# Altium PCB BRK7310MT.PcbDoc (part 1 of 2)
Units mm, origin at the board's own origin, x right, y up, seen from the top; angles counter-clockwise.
Board outline 140 x 100 mm, 6 copper layers (L1-TOP, L2-GND, L3-SIG, L4-SIG, L5-GND, L6-BOT), stack 1.39 mm thick; 75 components, 182 nets, 687 pads, 296 vias.
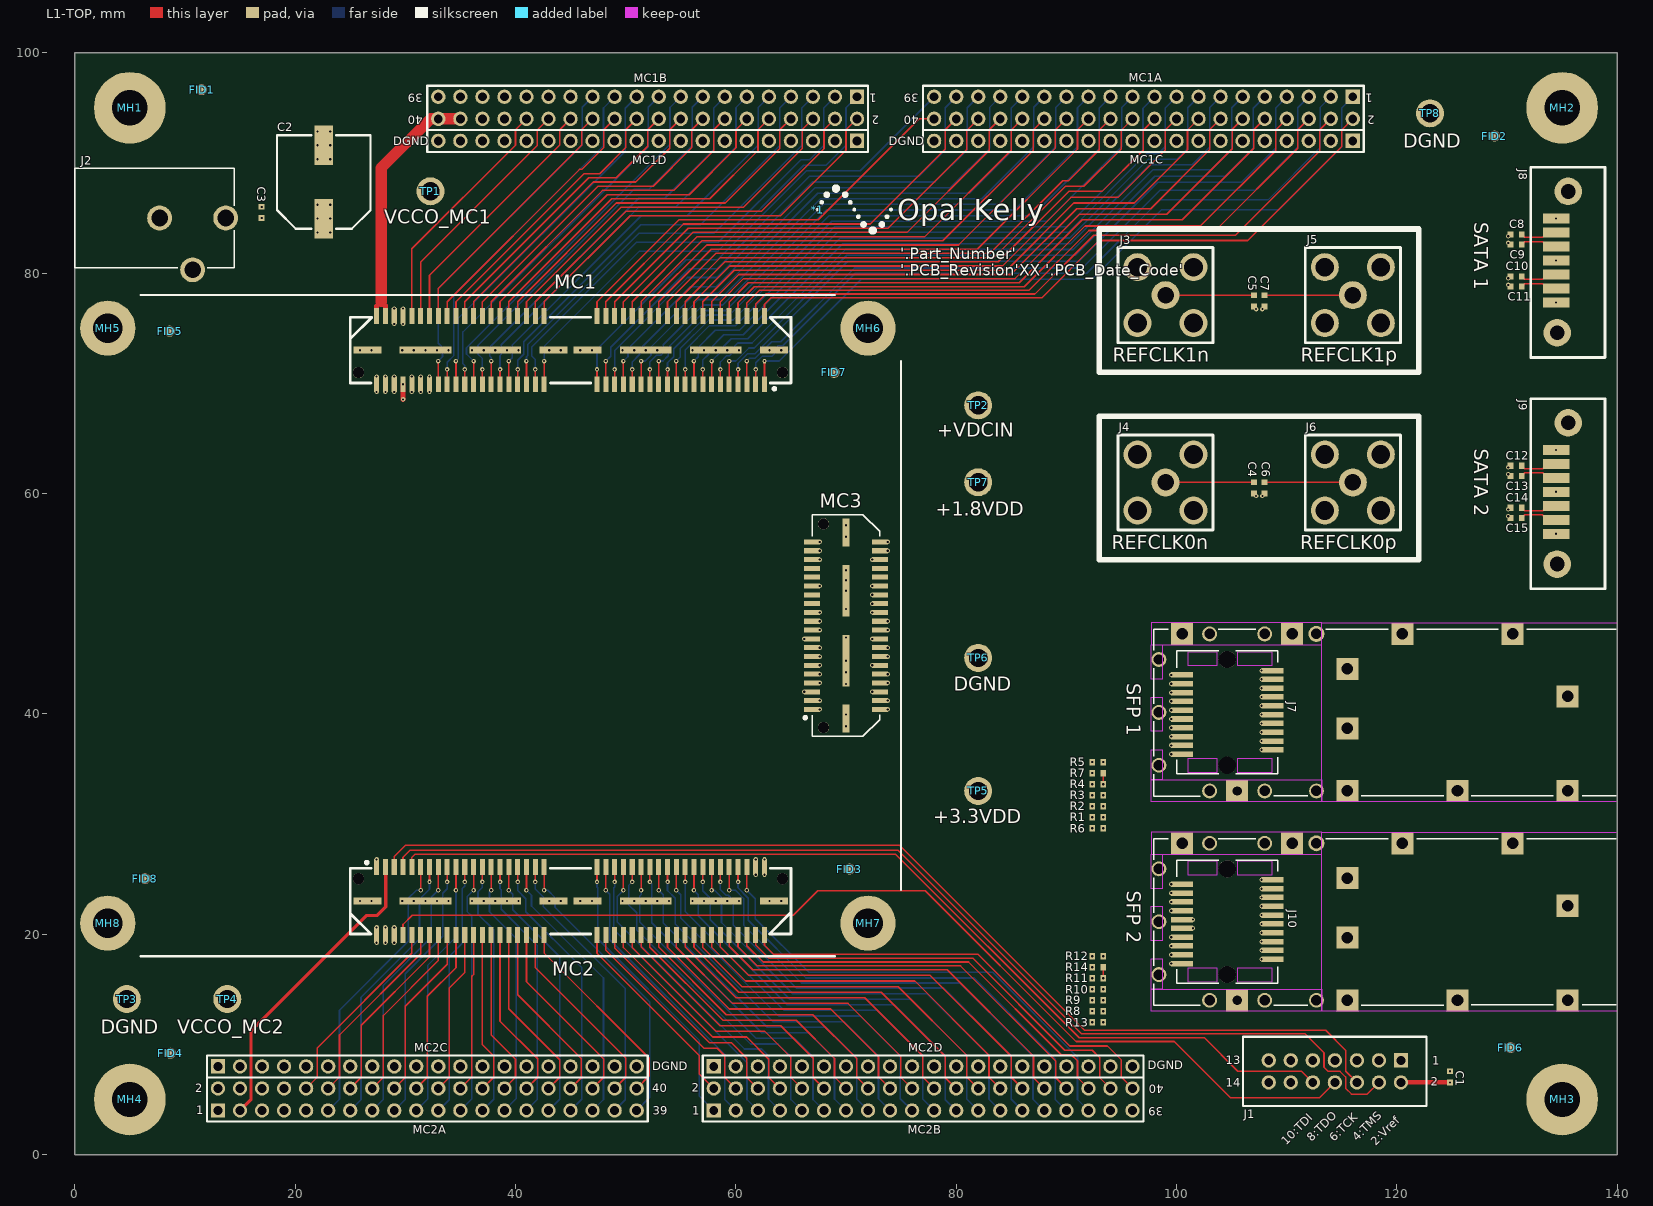
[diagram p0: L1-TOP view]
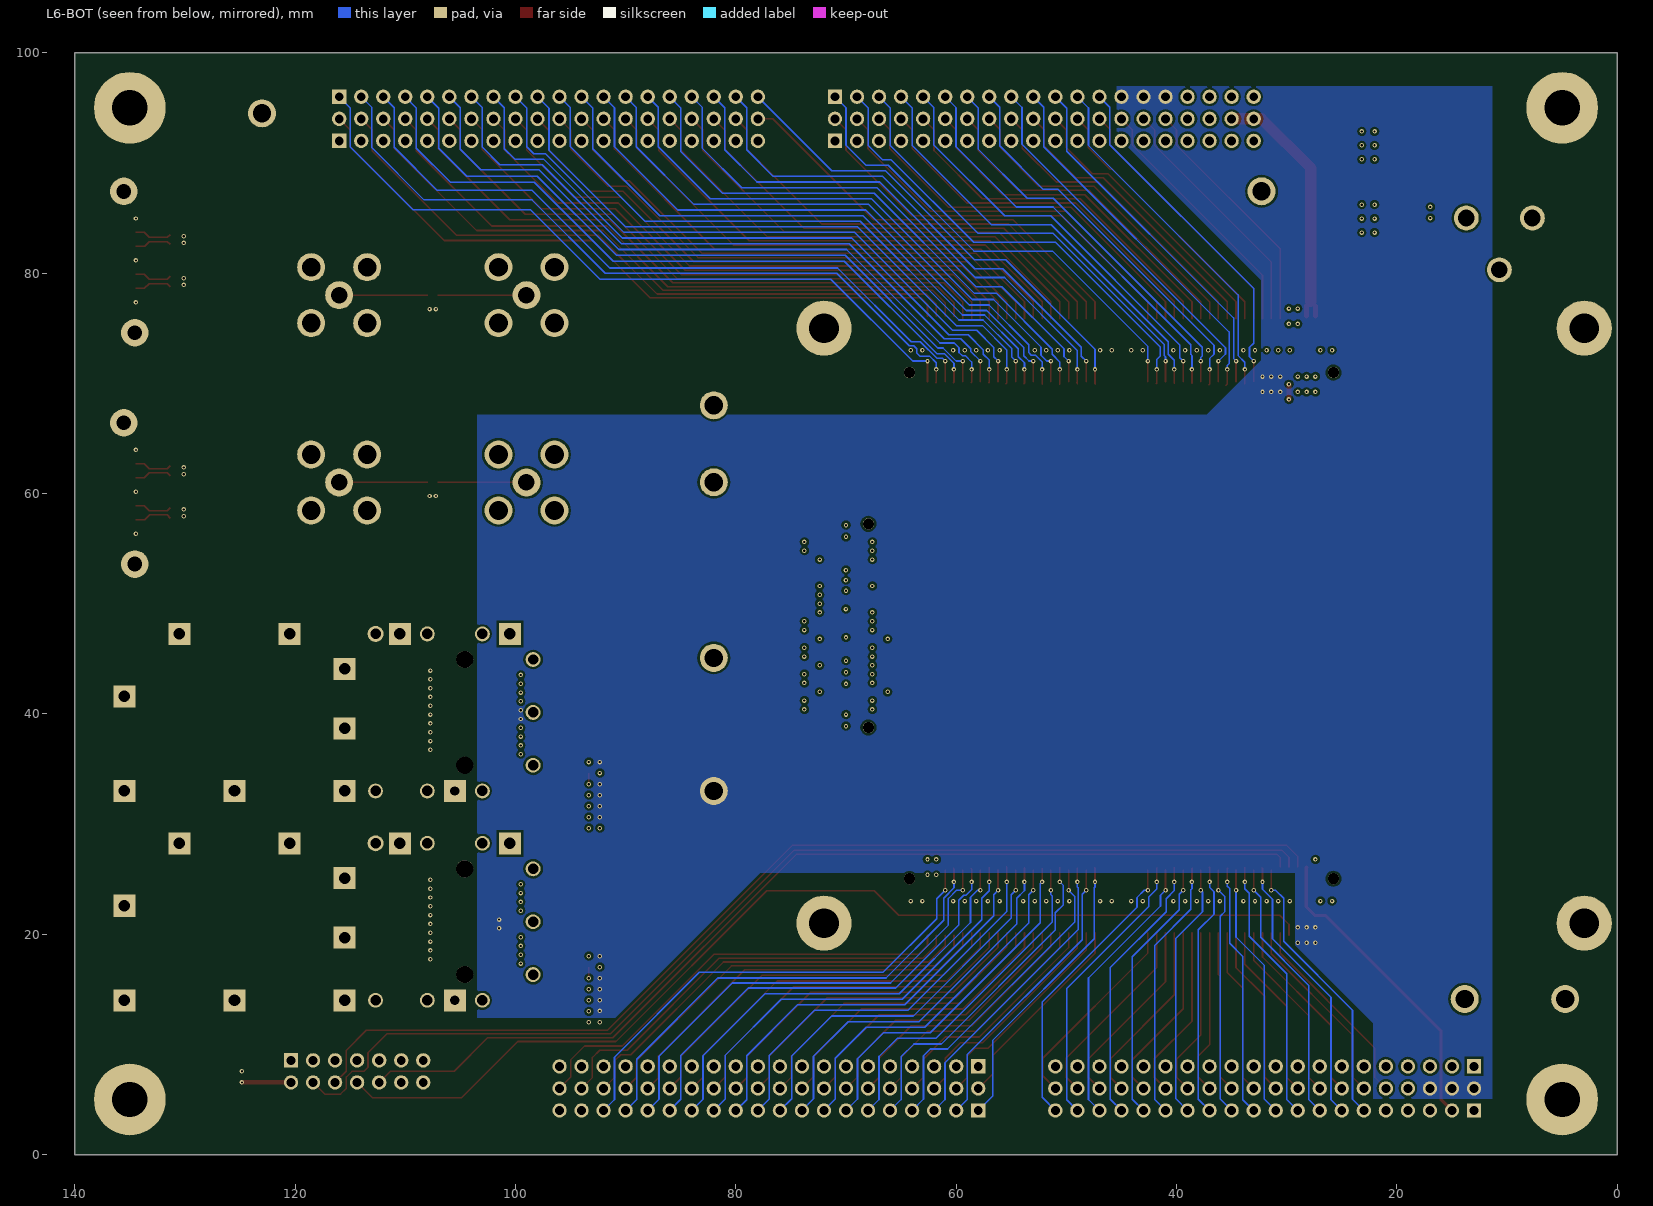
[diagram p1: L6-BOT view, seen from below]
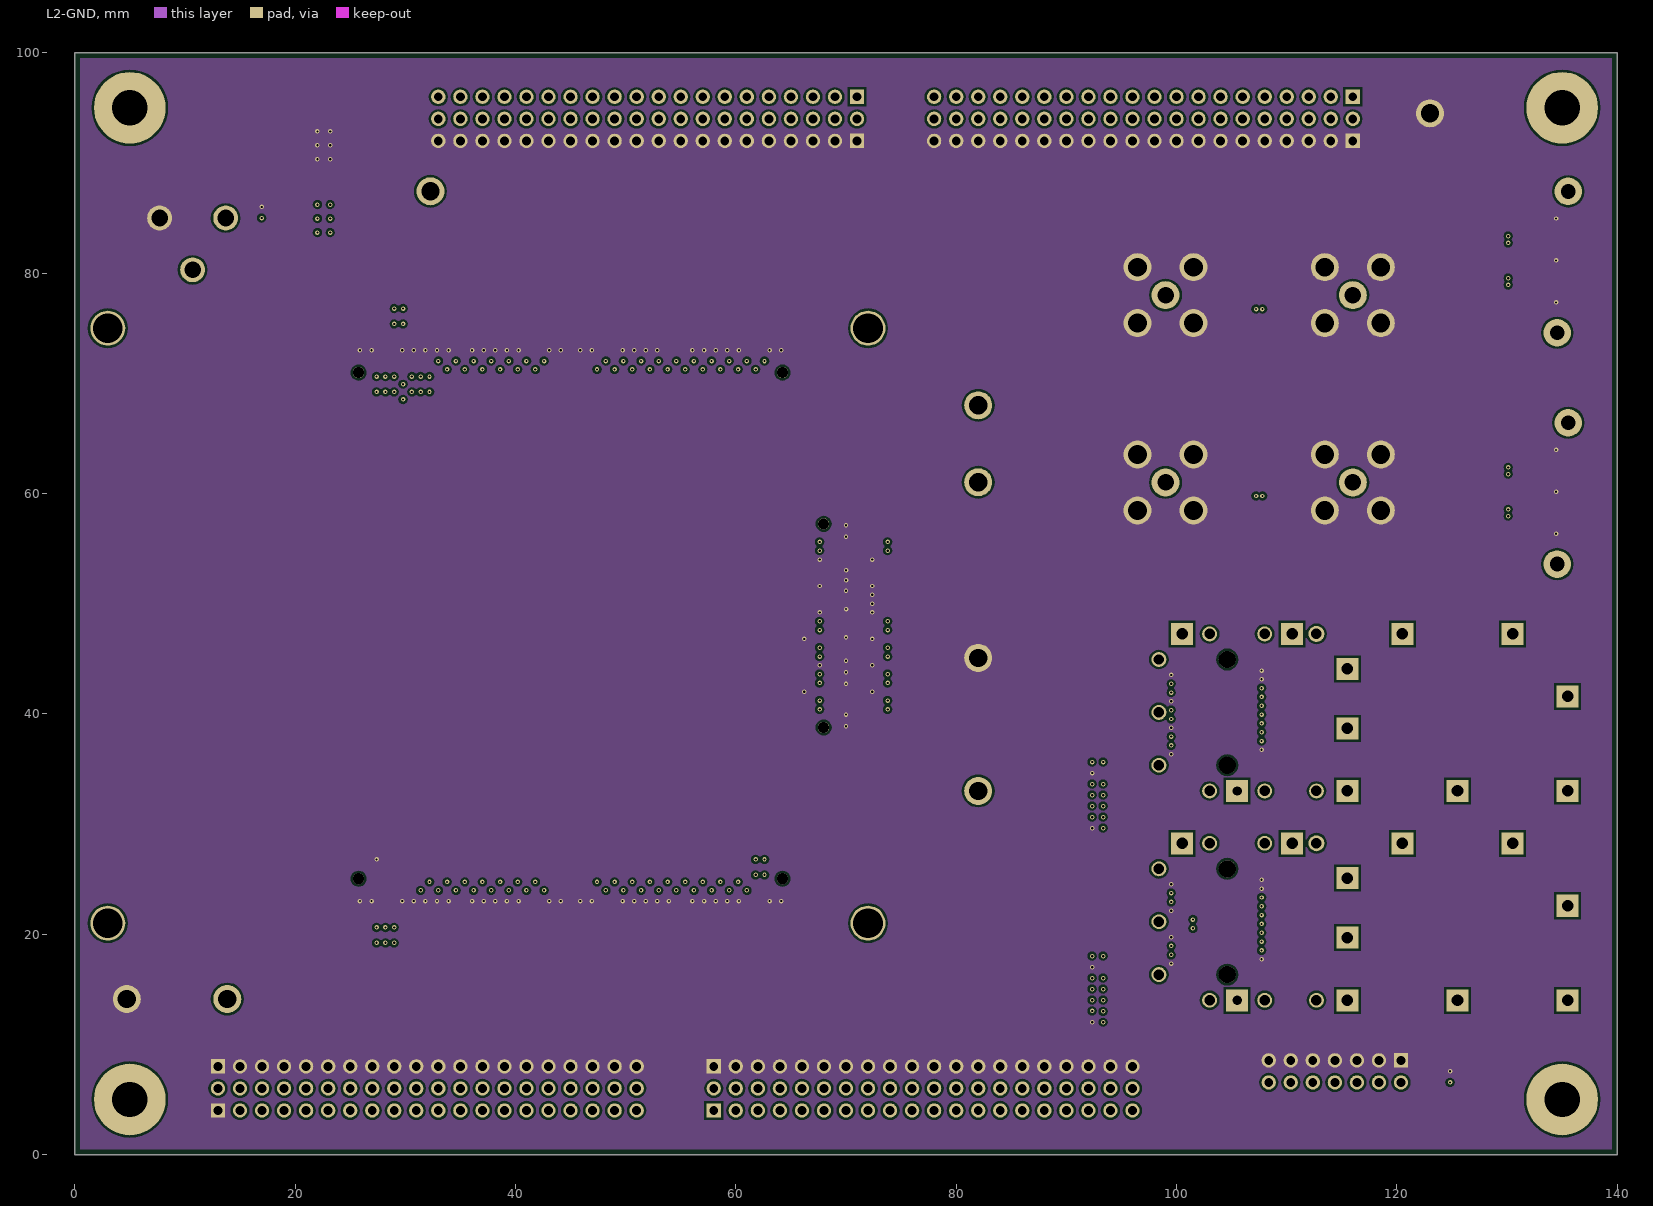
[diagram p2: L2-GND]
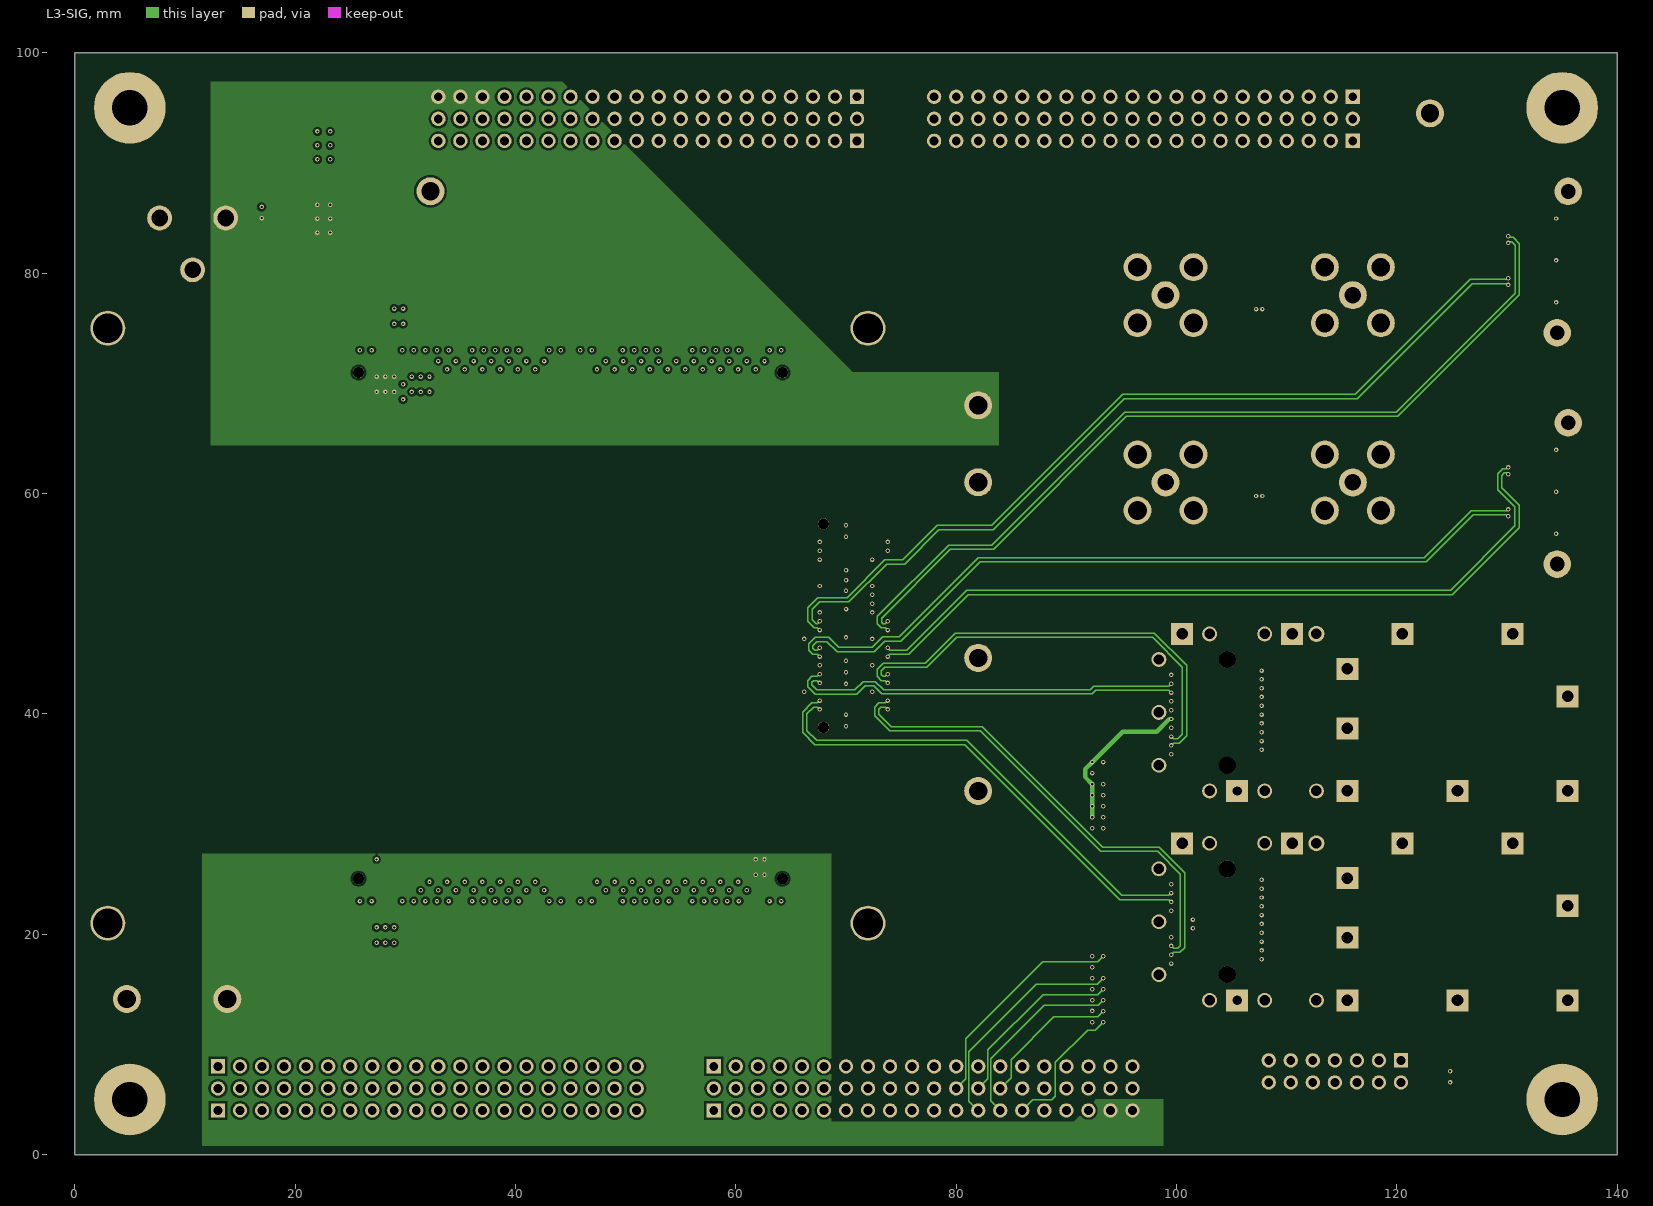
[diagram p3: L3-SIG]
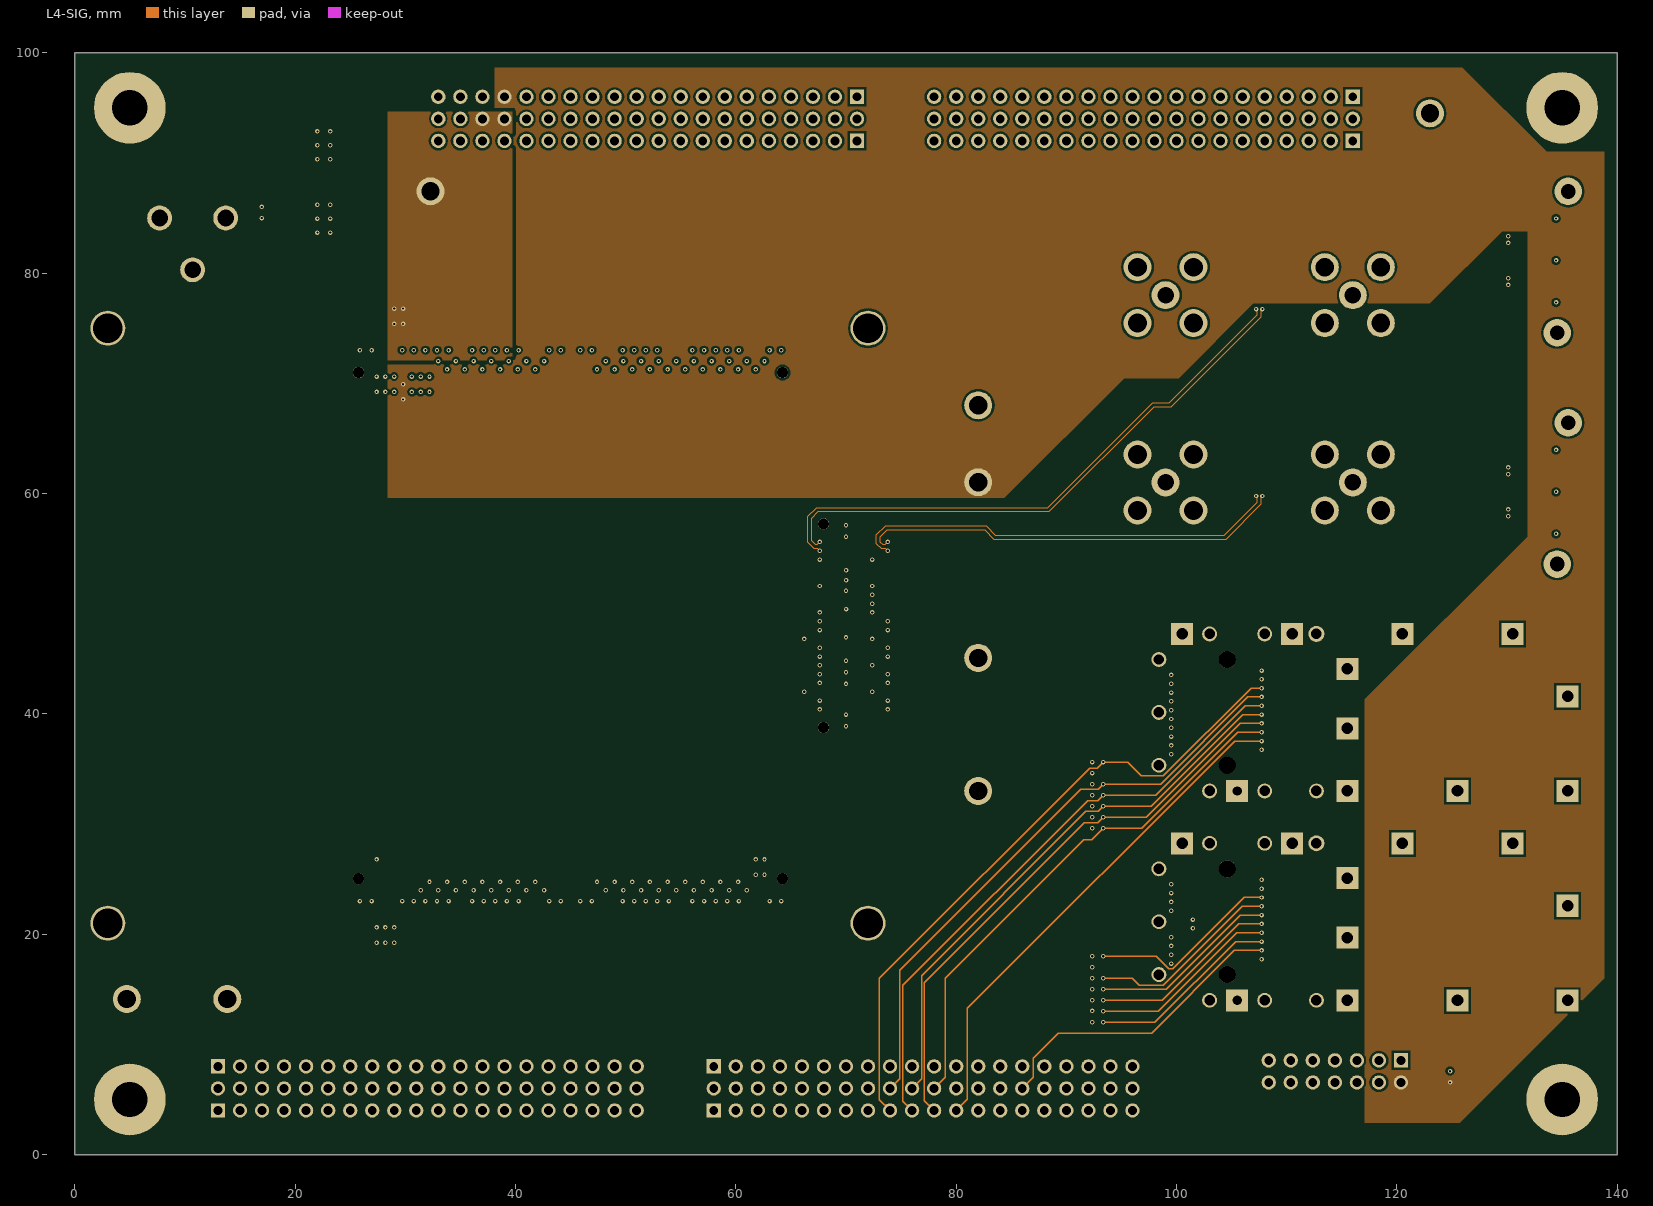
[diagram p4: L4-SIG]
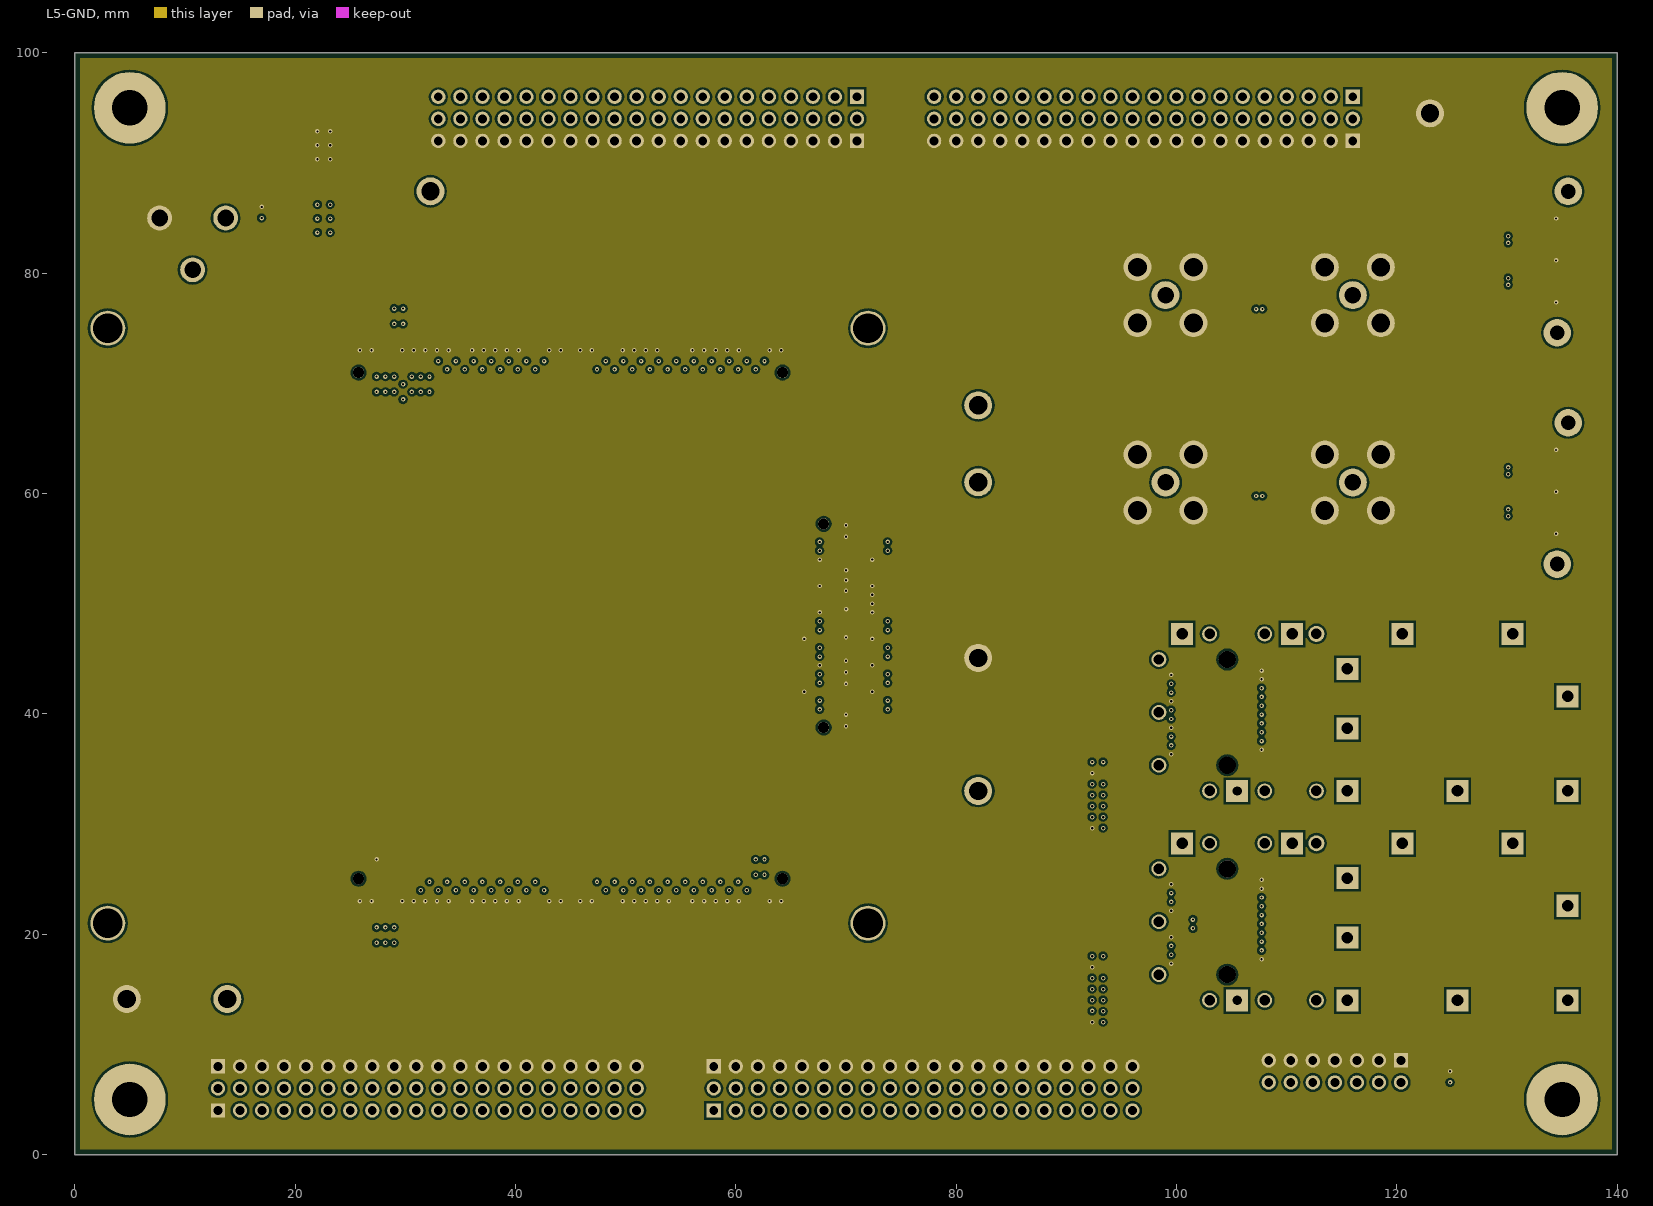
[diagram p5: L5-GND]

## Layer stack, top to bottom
Top Solder: solder mask 0.0203, Solder Resist, Dk 0
L1-TOP: signal copper 0.0356
Dielectric 2: prepreg 0.111, IT180A, Dk 4.12
L2-GND: signal copper 0.0356
Dielectric 5: core 0.0584, IT180A, Dk 4.12
L3-SIG: signal copper 0.0356
Dielectric 6: prepreg 0.8379, IT180A, Dk 4.2
L4-SIG: signal copper 0.0356
Dielectric 1: core 0.0584, IT180A, Dk 4.12
L5-GND: signal copper 0.0356
Dielectric 4: prepreg 0.111, IT180A, Dk 4.12
L6-BOT: signal copper 0.0356
Solder Side: solder mask 0.0203, Solder Resist, Dk 0

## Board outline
0,0 0,100 140,100 140,0

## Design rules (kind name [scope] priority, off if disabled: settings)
Clearance [All] p1: gap=0.127 ignorepadtopadclearanceinfootprint=FALSE except(0.114: SMDPad-Via Via-Via; 0.203: Arc-Poly SMDPad-Poly THPad-Poly Via-Fill Via-Poly Via-Region Fill-Poly Poly-Region Poly-Text Poly-Hole; 0.254: Track-Poly; 0.381: Poly-Poly)
DiffPairsRouting 100ohm_Diff [InDifferentialPairClass('100ohm_Diff')] p1: maxlimit=0.254 minlimit=0.248 mostfreqgap=0.254 toplayer_maxgap=0.248 toplayer_prefgap=0.248 toplayer_minwidth=0.133 toplayer_maxwidth=0.133 toplayer_prefwidth=0.133 midlayer1_mingap=0.254 midlayer1_minwidth=0.381 midlayer1_maxwidth=0.381 midlayer1_prefwidth=0.381 midlayer2_mingap=0.254 midlayer2_minwidth=0.127 midlayer2_maxwidth=0.127 midlayer2_prefwidth=0.127 midlayer3_mingap=0.254 midlayer3_minwidth=0.102 midlayer3_maxwidth=0.127 midlayer3_prefwidth=0.127 midlayer5_mingap=0.254 midlayer5_minwidth=0.381 midlayer5_maxwidth=0.381 midlayer5_prefwidth=0.381 bottomlayer_maxgap=0.248 bottomlayer_prefgap=0.248 bottomlayer_minwidth=0.133 bottomlayer_maxwidth=0.133 bottomlayer_prefwidth=0.133 maxuncoupledlength=8.89
FabricationTestPointUsage TestPointUsage [All] p1: valid=0 allowmultiple=FALSE
FabricationTestpoint Testpoint [All] p1: side=3 testpointundercomponent=TRUE minsize=1.016 maxsize=2.54 preferedsize=1.524 minholesize=0 maxholesize=1.016 preferedholesize=0.813 testpointgrid=0.025 allowsidetop=TRUE allowsidebottom=TRUE usegrid=TRUE gridtolerance=0
HoleSize [All] p1: absolutevalues=TRUE maxlimit=3.81 minlimit=0.203 maxpercent=80.000 minpercent=20.000
MatchedLengths okMatched_100ohm_Diff [InxSignalClass('xSignals_100ohm_Diff')] p1: tolerance=0.127 checknetsindiffpair=TRUE checkdiffpairvsdiffpair=FALSE checkxsignals=FALSE checkothers=FALSE
MinimumAnnularRing [All] p1: minimumring=0.102
MinimumSolderMaskSliver [All] p1: minsoldermaskwidth=0.048
PlaneClearance [All] p1: clearance=0.305
PlaneConnect [All] p1: planeconnectstyle=Direct reliefexpansion=0.508 reliefentries=4 reliefconductorwidth=0.254 reliefairgap=0.254
PolygonConnect "Via Connect" [IsVia] p1: connectstyle=Direct reliefconductorwidth=0.254 reliefentries=4 polygonreliefangle="90 Angle" airgapwidth=0.254
PolygonConnect [All] p2: connectstyle=Direct reliefconductorwidth=0.305 reliefentries=4 polygonreliefangle="90 Angle" airgapwidth=0.254
RoutingVias [All] p1: holewidth=0.203 width=0.406 viastyle="Through Hole" minholewidth=0.203 minwidth=0.406 maxholewidth=1.27 maxwidth=2.54
SilkToSilkClearance [All] p1: silktosilkclearance=0.003
SilkToSolderMaskClearance SilkscreenOverComponentPads [IsPad] p1: minsilkscreentomaskgap=0.051 clearancetoexposedcopper=TRUE
SolderMaskExpansion [All] p1: expansion=0.051
Width okWidth_50ohm [InNetClass('50ohm')] p1: maxlimit=0.254 minlimit=0.114 preferedwidth=0.117 toplayer_maxwidth=0.114 toplayer_prefwidth=0.114 midlayer1_minwidth=0.254 midlayer1_prefwidth=0.254 midlayer2_minwidth=0.117 midlayer2_maxwidth=0.117 midlayer3_minwidth=0.117 midlayer3_maxwidth=0.117 midlayer5_minwidth=0.254 midlayer5_prefwidth=0.254 bottomlayer_maxwidth=0.114 bottomlayer_prefwidth=0.114 minimp=50.000000 maximp=50.000000 favimp=50.000000
Width okWidth [All] p2: maxlimit=3.81 minlimit=0.102 preferedwidth=0.2 toplayer_prefwidth=0.127 midlayer1_prefwidth=0.127 midlayer2_prefwidth=0.127 midlayer3_prefwidth=0.127 midlayer5_minwidth=0.2 midlayer5_maxwidth=0.2 bottomlayer_prefwidth=0.127 minimp=50.000000 maximp=50.000000 favimp=50.000000
21 further rules are at their usual default settings.

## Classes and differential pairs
differential pair class 100ohm_Diff: DP_MGTREFCLK0 DP_MGTREFCLK0_C DP_MGTREFCLK1 DP_MGTREFCLK1_C DP_SATA_1_TXA DP_SATA_1_TXA_C DP_SATA_1_TXB DP_SATA_1_TXB_C DP_SATA_2_TXA DP_SATA_2_TXA_C DP_SATA_2_TXB DP_SATA_2_TXB_C DP_SFP1_RD DP_SFP1_TD DP_SFP2_RD DP_SFP2_TD
differential pair DP_MGTREFCLK0: +MGTREFCLK0P -MGTREFCLK0N
differential pair DP_MGTREFCLK1: +MGTREFCLK1P -MGTREFCLK1N
differential pair DP_SATA_1_TXA_C: +SATA_1_TXA+_C -SATA_1_TXA-_C
differential pair DP_SATA_1_TXA: +SATA_1_TXA+ -SATA_1_TXA-
differential pair DP_SATA_1_TXB_C: +SATA_1_TXB+_C -SATA_1_TXB-_C
differential pair DP_SATA_1_TXB: +SATA_1_TXB+ -SATA_1_TXB-
differential pair DP_SATA_2_TXA_C: +SATA_2_TXA+_C -SATA_2_TXA-_C
differential pair DP_SATA_2_TXA: +SATA_2_TXA+ -SATA_2_TXA-
differential pair DP_SATA_2_TXB_C: +SATA_2_TXB+_C -SATA_2_TXB-_C
differential pair DP_SATA_2_TXB: +SATA_2_TXB+ -SATA_2_TXB-
differential pair DP_SFP1_RD: +SFP1_RD_P -SFP1_RD_N
differential pair DP_SFP1_TD: +SFP1_TD_P -SFP1_TD_N
differential pair DP_SFP2_RD: +SFP2_RD_P -SFP2_RD_N
differential pair DP_SFP2_TD: +SFP2_TD_P -SFP2_TD_N

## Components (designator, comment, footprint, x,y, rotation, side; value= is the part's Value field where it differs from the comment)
*1 "Opal Kelly Logo" okLogo-23x5 67.422,85.767 r0 top
C1 "SM-0402, 10%, 10v" CAPC1005X06A 124.822,7.058 r270 top value="0.1 u"
C2 "EEE-FK1E221P" CAPAE9083X70N 22.606,88.269 r90 top locked value=220u
C3 "TMK105BJ104KV-F" CAPC1005X06A 16.967,85.5 r270 top value="0.1 u"
C4 "SM-0402, 10%, 10v" CAPC1005X06A 107.036,60.507 r270 top value="0.1 u"
C5 "SM-0402, 10%, 10v" CAPC1005X06A 107.036,77.474 r270 top value="0.1 u"
C6 "SM-0402, 10%, 10v" CAPC1005X06A 107.975,60.507 r270 top value="0.1 u"
C7 "SM-0402, 10%, 10v" CAPC1005X06A 107.975,77.474 r270 top value="0.1 u"
C8 "SM-0402, 10%, 10v" CAPC1005X06A 130.818,83.502 r180 top value="0.1 u"
C9 "SM-0402, 10%, 10v" CAPC1005X06A 130.818,82.605 r180 top value="0.1 u"
C10 "SM-0402, 10%, 10v" CAPC1005X06A 130.818,79.692 r180 top value="0.1 u"
C11 "SM-0402, 10%, 10v" CAPC1005X06A 130.818,78.778 r180 top value="0.1 u"
C12 "SM-0402, 10%, 10v" CAPC1005X06A 130.818,62.512 r180 top value="0.1 u"
C13 "SM-0402, 10%, 10v" CAPC1005X06A 130.818,61.598 r180 top value="0.1 u"
C14 "SM-0402, 10%, 10v" CAPC1005X06A 130.818,58.702 r180 top value="0.1 u"
C15 "SM-0402, 10%, 10v" CAPC1005X06A 130.818,57.763 r180 top value="0.1 u"
FID1 "FIDUCIAL" FID1MM/2MM-SS 11.506,96.647 r90 top
FID2 "FIDUCIAL" FID1MM/2MM-SS 128.854,92.43 r90 top
FID3 "FIDUCIAL" FID1MM/2MM-SS 70.307,25.908 r90 top
FID4 "FIDUCIAL" FID1MM/2MM-SS 8.687,9.195 r90 top
FID5 "FIDUCIAL" FID1MM/2MM-SS 8.611,74.727 r90 top
FID6 "FIDUCIAL" FID1MM/2MM-SS 130.302,9.703 r90 top
FID7 "FIDUCIAL" FID1MM/2MM-SS 68.91,70.993 r90 top
FID8 "FIDUCIAL" FID1MM/2MM-SS 6.375,25.044 r90 top
J1 "87831-1420" XILINX-JTAG 114.369,7.546 r180 top
J2 "PJ-102AH" CUI-PJ102A 0,85 r270 top
J3 "REFCLK1n" SMA 99,78 r180 top
J4 "REFCLK0n" SMA 99,61 r180 top
J5 "REFCLK1p" SMA 116,78 r180 top
J6 "REFCLK0p" SMA 116,61 r180 top
J7 "UE75-A20-6000T" SFP_RCPT_20_CAGE 105.5,33 r180 top locked
J8 "67800-5005" MOLEX-67800-5005 135,81 r90 top locked
J9 "67800-5005" MOLEX-67800-5005 135,60 r90 top locked
J10 "UE75-A20-6000T" SFP_RCPT_20_CAGE 105.5,14 r180 top locked
MC1 "QTE-040-01-F-D-A" QTE-040-01-X-D-A 45,73 r180 top locked
MC1A "0877584016" HDR2X20-2MM 97,95 r180 top locked
MC1B "0877584016" HDR2X20-2MM 52,95 r180 top locked
MC1C "Header, 20-Pin, Single Row" HDR1X20-2MM 97,92 r180 top locked
MC1D "Header, 20-Pin, Single Row" HDR1X20-2MM 52,92 r180 top locked
MC2 "QTE-040-01-F-D-A" QTE-040-01-X-D-A 45,23 r0 top locked
MC2A "0877584016" HDR2X20-2MM 32,5 r0 top locked
MC2B "0877584016" HDR2X20-2MM 77,5 r0 top locked
MC2C "Header, 20-Pin, Single Row" HDR1X20-2MM 32,8 r0 top locked
MC2D "Header, 20-Pin, Single Row" HDR1X20-2MM 77,8 r0 top locked
MC3 "QTE-020-01-F-D-A" QTE-020-01-X-D-A 70,48 r90 top locked
MH1 "MTG" MTG-3.2/6.5-PTH 5,95 r0 top
MH2 "MTG" MTG-3.2/6.5-PTH 135,95 r0 top
MH3 "MTG" MTG-3.2/6.5-PTH 135,5 r0 top
MH4 "MTG" MTG-3.2/6.5-PTH 5,5 r0 top
MH5 "MTG" MTG-2.7/5.0-PTH 3,75 r180 top locked
MH6 "MTG" MTG-2.7/5.0-PTH 72,75 r180 top locked
MH7 "MTG" MTG-2.7/5.0-PTH 72,21 r180 top locked
MH8 "MTG" MTG-2.7/5.0-PTH 3,21 r180 top locked
R1 "CRCW04024K70JNED" RESC1005X06A 92.845,30.617 r0 top value="4.7 k"
R2 "CRCW04024K70JNED" RESC1005X06A 92.845,31.617 r0 top value="4.7 k"
R3 "CRCW04024K70JNED" RESC1005X06A 92.845,32.617 r0 top value="4.7 k"
R4 "CRCW04024K70JNED" RESC1005X06A 92.845,33.617 r0 top value="4.7 k"
R5 "CRCW04024K70JNED" RESC1005X06A 92.845,35.617 r0 top value="4.7 k"
R6 "CRCW04024K70JNED" RESC1005X06A 92.845,29.617 r180 top value="4.7 k"
R7 "CRCW04024K70JNED" RESC1005X06A 92.845,34.617 r180 top value="4.7 k"
R8 "CRCW04024K70JNED" RESC1005X06A 92.845,13 r0 top value="4.7 k"
R9 "CRCW04024K70JNED" RESC1005X06A 92.845,14.007 r0 top value="4.7 k"
R10 "CRCW04024K70JNED" RESC1005X06A 92.845,15.007 r0 top value="4.7 k"
R11 "CRCW04024K70JNED" RESC1005X06A 92.845,16.007 r0 top value="4.7 k"
R12 "CRCW04024K70JNED" RESC1005X06A 92.845,18.007 r0 top value="4.7 k"
R13 "CRCW04024K70JNED" RESC1005X06A 92.845,12.007 r180 top value="4.7 k"
R14 "CRCW04024K70JNED" RESC1005X06A 92.845,17.007 r180 top value="4.7 k"
TP1 "VCCO_MC1" TP-PTH-65/100#1 32.283,87.427 r0 top
TP2 "+VDCIN" TP-PTH-65/100#1 82,68 r0 top
TP3 "DGND" TP-PTH-65/100#1 4.724,14.113 r90 top
TP4 "VCCO_MC2" TP-PTH-65/100#2 13.843,14.101 r0 top
TP5 "+3.3VDD" TP-PTH-65/100#1 82,33 r0 top
TP6 "DGND" TP-PTH-65/100#3 82.011,45.201 r90 top
TP7 "+1.8VDD" TP-PTH-65/100#1 82,61.017 r0 top
TP8 "DGND" TP-PTH-65/100#1 123,94.5 r90 top

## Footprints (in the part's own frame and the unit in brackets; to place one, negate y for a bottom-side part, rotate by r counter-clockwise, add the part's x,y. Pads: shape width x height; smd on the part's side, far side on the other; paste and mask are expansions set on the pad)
CAPAE9083X70N [mm] "Aluminum Electrolytic Capacitor, Body 8.30x8.30x7.00mm, IPC Medium Density"
  rect 3.6x1.65 smd: 1(-3.325,0) 2(3.325,0)
  silkscreen extent -4.25,-4.25 4.25,4.25
CAPC1005X06A [mm] "Chip Capacitor, 2-Leads, Body 1.00x0.50mm, OK custom footprint"
  rect 0.52x0.55 smd mask+0.051: 1(-0.51,0) 2(0.51,0)
CUI-PJ102A [mm] "2.1mm/5.5mm DC power jack"
  round 2.25 hole 1.5: 1(0,13.7) 2(0,7.7) 3(4.7,10.7)
  silkscreen extent -4.5,0 4.5,14.5
FID1MM/2MM-SS [mm] "Fiducial 1mm copper, 2mm soldermask, single-side"
  round 1 smd paste-0.5 mask+0.5: FID?(0,0)
HDR1X20-2MM [mm] "2mm 1x20 Header"
  rect 1.3x1.3 hole 0.8: 1(-19,0)
  round 1.3 hole 0.8: 2(-17,0) 3(-15,0) 4(-13,0) 5(-11,0) 6(-9,0) 7(-7,0) 8(-5,0) 9(-3,0) 10(-1,0) 11(1,0) 12(3,0) 13(5,0) 14(7,0) 15(9,0) 16(11,0) 17(13,0) 18(15,0) 19(17,0) 20(19,0)
  silkscreen extent -20,-1 20,1
HDR2X20-2MM [mm] "2mm 2x20 header"
  rect 1.3x1.3 hole 0.8: 1(-19,-1)
  round 1.3 hole 0.8: 2(-19,1) 3(-17,-1) 4(-17,1) 5(-15,-1) 6(-15,1) 7(-13,-1) 8(-13,1) 9(-11,-1) 10(-11,1) 11(-9,-1) 12(-9,1) 13(-7,-1) 14(-7,1) 15(-5,-1) 16(-5,1) 17(-3,-1) 18(-3,1) 19(-1,-1) 20(-1,1) 21(1,-1) 22(1,1) 23(3,-1) 24(3,1) 25(5,-1) 26(5,1) 27(7,-1) 28(7,1) 29(9,-1) 30(9,1) 31(11,-1) 32(11,1) 33(13,-1) 34(13,1) 35(15,-1) 36(15,1) 37(17,-1) 38(17,1) 39(19,-1) 40(19,1)
  silkscreen extent -20,-2 20,2
MOLEX-67800-5005 [mm]
  rect 0.9x2.4 smd: 1(3.955,0.55) 2(2.685,0.55) 3(1.415,0.55) 4(0.145,0.55) 5(-1.125,0.55) 6(-2.395,0.55) 7(-3.665,0.55)
  round 2.5 hole 1.35: MH(-6.415,0.45) MH(6.415,-0.55)
  silkscreen extent -8.65,-3.9 8.6,2.85
MTG-2.7/5.0-PTH [mm] "Mounting hole, 2.7mm ID, 5.0mm OD, plated"
  round 5 / inner round 3.175 / far side round 5 hole 2.7: 1(0,0)
MTG-3.2/6.5-PTH [mm] "Mounting hole, 3.2mm ID, 6.5mm OD, plated"
  round 6.5 hole 3.2: 1(0,0)
okLogo-23x5 [mm] "Opal Kelly silkscreen logo (23mm x 5mm)"
  silkscreen extent -0.09,-2.1 6.75,2.1
QTE-020-01-X-D-A [mil] "0.80mm, 40 pin Surface Mount connectors with Ground Strip"
  rect 100x25 smd paste+0: 0(-332.5,0) 0(332.5,0)
  rect 185x25 smd paste+0: 0(-125,0) 0(125,0)
  rect 18x57 smd paste+0: 1(-299.25,121.5) 2(-299.25,-121.5) 3(-267.75,121.5) 4(-267.75,-121.5) 5(-236.25,121.5) 6(-236.25,-121.5) 7(-204.75,121.5) 8(-204.75,-121.5) 9(-173.25,121.5) 10(-173.25,-121.5) 11(-141.75,121.5) 12(-141.75,-121.5) 13(-110.25,121.5) 14(-110.25,-121.5) 15(-78.75,121.5) 16(-78.75,-121.5) 17(-47.25,121.5) 18(-47.25,-121.5) 19(-15.75,121.5) 20(-15.75,-121.5) 21(15.75,121.5) 22(15.75,-121.5) 23(47.25,121.5) 24(47.25,-121.5) 25(78.75,121.5) 26(78.75,-121.5) 27(110.25,121.5) 28(110.25,-121.5) 29(141.75,121.5) 30(141.75,-121.5) 31(173.25,121.5) 32(173.25,-121.5) 33(204.75,121.5) 34(204.75,-121.5) 35(236.25,121.5) 36(236.25,-121.5) 37(267.75,121.5) 38(267.75,-121.5) 39(299.25,121.5) 40(299.25,-121.5)
  round 40 hole 40 unplated paste+0: MH(-363.75,80) MH(363.75,80)
  silkscreen extent -396,-120 396,151
QTE-040-01-X-D-A [mil] "0.80mm, 80 pin Surface Mount connectors with Ground Strip"
  rect 100x25 smd paste+0: 0(-726.25,0) 0(-61.25,0) 0(61.25,0) 0(726.25,0)
  rect 185x25 smd paste+0: 0(-518.75,0) 0(-268.75,0) 0(268.75,0) 0(518.75,0)
  rect 18x57 smd paste+0: 1(-693,121.5) 2(-693,-121.5) 3(-661.5,121.5) 4(-661.5,-121.5) 5(-630,121.5) 6(-630,-121.5) 7(-598.5,121.5) 8(-598.5,-121.5) 9(-567,121.5) 10(-567,-121.5) 11(-535.5,121.5) 12(-535.5,-121.5) 13(-504,121.5) 14(-504,-121.5) 15(-472.5,121.5) 16(-472.5,-121.5) 17(-441,121.5) 18(-441,-121.5) 19(-409.5,121.5) 20(-409.5,-121.5) 21(-378,121.5) 22(-378,-121.5) 23(-346.5,121.5) 24(-346.5,-121.5) 25(-315,121.5) 26(-315,-121.5) 27(-283.5,121.5) 28(-283.5,-121.5) 29(-252,121.5) 30(-252,-121.5) 31(-220.5,121.5) 32(-220.5,-121.5) 33(-189,121.5) 34(-189,-121.5) 35(-157.5,121.5) 36(-157.5,-121.5) 37(-126,121.5) 38(-126,-121.5) 39(-94.5,121.5) 40(-94.5,-121.5) 41(94.5,121.5) 42(94.5,-121.5) 43(126,121.5) 44(126,-121.5) 45(157.5,121.5) 46(157.5,-121.5) 47(189,121.5) 48(189,-121.5) 49(220.5,121.5) 50(220.5,-121.5) 51(252,121.5) 52(252,-121.5) 53(283.5,121.5) 54(283.5,-121.5) 55(315,121.5) 56(315,-121.5) 57(346.5,121.5) 58(346.5,-121.5) 59(378,121.5) 60(378,-121.5) 61(409.5,121.5) 62(409.5,-121.5) 63(441,121.5) 64(441,-121.5) 65(472.5,121.5) 66(472.5,-121.5) 67(504,121.5) 68(504,-121.5) 69(535.5,121.5) 70(535.5,-121.5) 71(567,121.5) 72(567,-121.5) 73(598.5,121.5) 74(598.5,-121.5) 75(630,121.5) 76(630,-121.5) 77(661.5,121.5) 78(661.5,-121.5) 79(693,121.5) 80(693,-121.5)
  round 40 hole 40 unplated paste+0: MH(-757.5,80) MH(757.5,80)
  silkscreen extent -788,-118 788,143
RESC1005X06A [mm] "Chip Resistor, 2-Leads, Body 1.00x0.50mm, OK custom footprint"
  rect 0.5x0.6 smd mask+0.051: 1(-0.5,0) 2(0.5,0)
SFP_RCPT_20_CAGE [mm]
  rect 2x2 hole 1.05: 0(-30,-8.58) 0(-30,0) 0(-25,-14.25) 0(-20,0) 0(-15,-14.25) 0(-10,-5.68) 0(-10,0) 0(-10,-11.08) 0(-5,-14.25) 0(5,-14.25)
  round 1.35 hole 0.95: 0(-7.2,0) 0(-2.5,0) 0(-2.5,-14.25) 0(2.5,0) 0(2.5,-14.25) 0(7.1,-2.33) 0(7.1,-11.93) 0(7.1,-7.13)
  round 1.45 hole 0.95: 0(-7.2,-14.25)
  rect 2x2 hole 0.85: 0(0,0)
  rect 2x0.5 smd: 1(-3.2,-3.73) 2(-3.2,-4.53) 3(-3.2,-5.33) 4(-3.2,-6.13) 5(-3.2,-6.93) 6(-3.2,-7.73) 7(-3.2,-8.53) 8(-3.2,-9.33) 9(-3.2,-10.13) 10(-3.2,-10.93) 11(5,-10.53) 12(5,-9.73) 13(5,-8.93) 14(5,-8.13) 15(5,-7.33) 16(5,-6.53) 17(5,-5.73) 18(5,-4.93) 19(5,-4.13) 20(5,-3.33)
  round 1.55 hole 1.55 unplated: MH(0.9,-2.33) MH(0.9,-11.93)
  L1-TOP keep-out region: -3.2,-12.6 0,-12.6 0,-11.4 -3.2,-11.4
  L1-TOP keep-out region: 1.8,-12.6 4.5,-12.6 4.5,-11.4 1.8,-11.4
  L1-TOP keep-out region: 1.8,-2.9 4.5,-2.9 4.5,-1.7 1.8,-1.7
  L1-TOP keep-out region: -3.2,-2.9 0,-2.9 0,-1.7 -3.2,-1.7
  L1-TOP keep-out region: 7.8,-3.75 6.8,-3.75 6.8,-1 7.8,-1
  L1-TOP keep-out region: 7.8,-13.25 6.8,-13.25 6.8,-10.125 7.8,-10.125
  L1-TOP keep-out region: -7.7,1 7.8,1 7.8,-1 -7.7,-1
  L1-TOP keep-out region: -7.7,-15.25 7.8,-15.25 7.8,-13.25 -7.7,-13.25
  L1-TOP keep-out region: -34.5,1 -7.7,1 -7.7,-15.25 -34.5,-15.25
  L1-TOP keep-out region: 7.8,-8.525 6.8,-8.525 6.8,-5.4 7.8,-5.4
  silkscreen extent -34.4,-14.68 7.55,0.47
SMA [mil] "PCB-mount SMA connector"
  round 100 hole 59: 1(0,0)
  round 100 hole 67: 2(-100,100) 2(-100,-100) 2(100,100) 2(100,-100)
  Top Overlay keep-out lines w10: 170,170 -170,170 -170,-170 170,-170 170,170
  silkscreen extent -170,-170 170,170
TP-PTH-65/100#1 [mil] "Test point, plated through-hole, 65/100mil"
  round 100 hole 65: 1(0,0)
TP-PTH-65/100#2 [mil] "Test point, plated through-hole, 65/100mil"
  round 100 hole 65: 1(0,0.49)
TP-PTH-65/100#3 [mil] "Test point, plated through-hole, 65/100mil"
  round 100 hole 65: 1(-4.91,0.44)
XILINX-JTAG [mm] "2mm 2x7 header"
  rect 1.3x1.3 hole 0.8: 1(-6,-1)
  round 1.3 hole 0.8: 2(-6,1) 3(-4,-1) 4(-4,1) 5(-2,-1) 6(-2,1) 7(0,-1) 8(0,1) 9(2,-1) 10(2,1) 11(4,-1) 12(4,1) 13(6,-1) 14(6,1)
  silkscreen extent -8.32,-3.15 8.32,3.15

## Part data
*1: library part OKLOGO
C1 C4 C5 C6 C7 C8 C9 C10 C11 C12 C13 C14 C15: library part 000070, Manufacturer=Kemet, Manufacturer_PN=C0402C104K8PACTU, ValueFloat=1E-7, x_tolerance=10
C2: library part 001532, "Polarized", Manufacturer=Panasonic, ValueFloat=0.00022, Voltage=25V, x_tolerance=20, x_voltage-rating=25
C3: library part 001073, "Ceramic capacitor", Manufacturer="Taiyo Yuden", Tolerance (%)=10, ValueFloat=1E-7, Voltage=25V
FID1 FID2 FID3 FID4 FID5 FID6 FID7 FID8: "PCB fiducial"
J1: library part 000541, "2mm header, shrouded", Manufacturer=Molex
J2: library part 000356, "DC power connector - high current", Manufacturer="CUI Inc."
J3 J4 J5 J6: library part 000974, "Straight SMA PCB Mount", Manufacturer=Amphenol, Manufacturer_PN=901-144-8RFX
J7 J10: library part 000986, "SFP 20-POS Recepticle", Manufacturer=Amphenol
J8 J9: library part 000988, "SATA 7-pin receptacle", Manufacturer=Molex
MC1 MC2: library part QTE_QSE-040, "0.8mm hi-speed, high-density header (female)", Manufacturer=Samtec, partnumber=000972
MC1A MC1B: library part "Header 20X2", "2mm header, 20x2, thru-hole", Manufacturer=Molex, partnumber=000583
MC1C MC1D: library part "Header 1X20", "2mm header, 20x1, thru-hole", Manufacturer=3M, Manufacturer_PN=951120-8622-AR, partnumber=001334
MC2A MC2B: library part 000583, Manufacturer=Molex
MC2C MC2D: library part 001334, Manufacturer=3M, Manufacturer_PN=951120-8622-AR
MC3: library part QTE_QSE-020, "0.8mm hi-speed, high-density header (female)", Manufacturer=Samtec, partnumber=000973
MH1 MH2 MH3 MH4 MH5 MH6 MH7 MH8: "Mounting hole"
R1 R2 R3 R4 R5 R6 R7 R8 R9 R10 R11 R12 R13 R14: library part Resistor, "Thick-film resistor", Manufacturer=Vishay, partnumber=000754, ValueFloat=4700.0
TP1 TP2 TP3 TP4 TP5 TP6 TP7 TP8: library part TP-PTH-65/100, "Test point, plated through-hole, 65/100mil"

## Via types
v1: diameter 0.406, hole 0.203, L1-TOP to L6-BOT, tented both sides, 296 vias

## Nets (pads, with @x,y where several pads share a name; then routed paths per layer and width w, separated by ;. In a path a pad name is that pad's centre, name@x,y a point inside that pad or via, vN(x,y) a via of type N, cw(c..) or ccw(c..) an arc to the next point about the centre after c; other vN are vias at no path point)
+1.0VDD: MC1.78 MC1.80 MC1B.38 MC1B.40 | length 24.2
  L1-TOP w0.432: MC1.80@27.398,76.086 27.398,77.029 27.813,77.445 28.198,77.06 MC1.78@28.198,76.086
  L1-TOP w1.016: 27.813,77.445 27.813,89.535 32.278,94 MC1B.40@33,94 MC1B.38@35,94
+1.8VDD: C1.2 J1.2 MC1.73 MC1B.33 TP7.1 | length 5.8
  L1-TOP w0.406: J1.2@120.369,6.546 124.819,6.546 v1(124.822,6.548)
  L1-TOP w0.432: v1(29.798,68.529) v1(29.798,69.914)
+3.3VDD: J7.15 J7.16 J10.15 J10.16 MC1.67 MC1.69 MC1.71 MC1B.27 MC1B.29 MC1B.31 MC2.2 MC2.4 MC2.6 MC2A.2 MC2A.4 MC2A.6 R1.1 R2.1 R3.1 R4.1 R5.1 R8.1 R9.1 R10.1 R11.1 R12.1 TP5.1 | length 14.3
  L3-SIG w0.406: v1(92.345,30.617) v1(92.345,31.617) v1(92.345,32.617) v1(92.345,33.617) 91.694,34.268 91.694,34.966 v1(92.345,35.617) 95.111,38.383 98.196,38.383 99.343,39.53 v1(99.517,39.53)
  other v1: 92.345,13.037 92.345,14.007 92.345,15.007 92.345,16.007 92.345,18.007 27.398,19.216 28.198,19.216 28.998,19.216 101.483,20.53 27.398,20.612 28.198,20.612 28.998,20.612 101.483,21.33 99.517,40.33 30.598,69.216 31.398,69.216 32.198,69.216 30.598,70.612 31.398,70.612 32.198,70.612
+VDCIN: C2.1 C3.2 J2.1 MC1.75 MC1.77 MC1.79 MC1B.35 MC1B.37 MC1B.39 TP2.1
  other v1: 27.398,69.216 28.198,69.216 28.998,69.216 27.398,70.612 28.198,70.612 28.998,70.612 22.022,83.676 23.19,83.676 22.022,84.944 23.19,84.944 16.967,84.99 22.022,86.211 23.19,86.211
DGND: C1.1 C2.2 C3.1 J1.1 J1.3 J1.5 J1.7 J1.9 J1.11 J1.13 J2.2 J3.2 J4.2 J5.2 J6.2 J7.1 J7.9 J7.10 J7.11 J7.14 J7.17 J7.20 J8.1 J8.4 J8.7 J9.1 J9.4 J9.7 J10.1 J10.9 J10.10 J10.11 J10.14 J10.17 J10.20 MC1.0 MC1C.1 MC1C.2 MC1C.3 MC1C.4 MC1C.5 MC1C.6 MC1C.7 MC1C.8 MC1C.9 MC1C.10 MC1C.11 MC1C.12 MC1C.13 MC1C.14 MC1C.15 MC1C.16 MC1C.17 MC1C.18 MC1C.19 MC1C.20 MC1D.1 MC1D.2 MC1D.3 MC1D.4 MC1D.5 MC1D.6 MC1D.7 MC1D.8 MC1D.9 MC1D.10 MC1D.11 MC1D.12 MC1D.13 MC1D.14 MC1D.15 MC1D.16 MC1D.17 MC1D.18 MC1D.19 MC1D.20 MC2.0 MC2.1 MC2A.1 MC2C.1 MC2C.2 MC2C.3 MC2C.4 MC2C.5 MC2C.6 MC2C.7 MC2C.8 MC2C.9 MC2C.10 MC2C.11 MC2C.12 MC2C.13 MC2C.14 MC2C.15 MC2C.16 MC2C.17 MC2C.18 MC2C.19 MC2C.20 MC2D.1 MC2D.2 MC2D.3 MC2D.4 MC2D.5 MC2D.6 MC2D.7 MC2D.8 MC2D.9 MC2D.10 MC2D.11 MC2D.12 MC2D.13 MC2D.14 MC2D.15 MC2D.16 MC2D.17 MC2D.18 MC2D.19 MC2D.20 MC3.0 MC3.5 MC3.6 MC3.11 MC3.12 MC3.17 MC3.18 MC3.23 MC3.24 MC3.26 MC3.28 MC3.29 MC3.30 MC3.35 MC3.36 R6.2 R7.2 R13.2 R14.2 TP3.1 TP6.1 TP8.1
  other v1: 124.822,7.568 92.345,12.007 92.345,17.007 99.517,17.33 107.717,17.73 99.517,19.73 99.517,22.13 25.881,23 26.936,23 29.717,23 30.771,23 31.825,23 32.879,23 33.933,23 36.067,23 37.121,23 38.175,23 39.229,23 40.283,23 43.065,23 44.119,23 45.881,23 46.935,23 49.717,23 50.771,23 51.825,23 52.879,23 53.933,23 56.067,23 57.121,23 58.175,23 59.229,23 60.283,23 63.064,23 64.119,23 107.717,24.13 99.517,24.53 107.717,24.93 27.398,26.784 92.345,29.617 92.345,34.617 99.517,36.33 107.717,36.73 99.517,38.73 70,38.881 70,39.935 99.517,41.13 66.218,41.999 72.39,41.999 70,42.717 107.717,43.13 99.517,43.53 70,43.771 107.717,43.93 67.61,44.4 72.39,44.4 70,44.825 66.218,46.8 72.39,46.8 70,46.933 67.61,49.2 72.39,49.2 70.002,49.508 72.39,50 72.39,50.8 70,51.175 67.61,51.6 72.39,51.6 70.002,52.125 70.002,53.039 67.61,54.001 72.39,54.001 70,56.064 134.45,56.335 70,57.119 134.45,60.145 134.45,63.955 25.881,73 26.935,73 29.717,73 30.771,73 31.825,73 32.879,73 33.933,73 36.067,73 37.121,73 38.175,73 39.229,73 40.283,73 43.064,73 44.119,73 45.881,73 46.935,73 49.717,73 50.771,73 51.825,73 52.879,73 56.067,73 57.121,73 58.175,73 59.229,73 60.283,73 63.064,73 64.119,73 134.45,77.335 134.45,81.145 134.45,84.955 16.967,86.01 22.022,90.326 23.19,90.326 22.022,91.594 23.19,91.594 22.022,92.861 23.19,92.861
FPGA_TCK: J1.6 MC2.5 | length 98.8
  L1-TOP w0.146: MC2.5@28.998,26.086 28.998,27.042 30.023,28.067 74.854,28.067 91.643,11.278 113.538,11.278 115.367,9.449 115.367,7.548 J1.6@116.369,6.546
FPGA_TDI: J1.10 MC2.9 | length 91.3
  L1-TOP w0.146: MC2.9@30.598,26.086 30.598,26.966 30.886,27.254 74.498,27.254 91.161,10.592 102.54,10.592 105.562,7.569 111.346,7.569 J1.10@112.369,6.546
FPGA_TDO: J1.8 MC2.8 | length 95.2
  L1-TOP w0.146: MC2.8@29.798,19.914 29.798,20.883 30.645,21.73 65.214,21.73 67.436,23.952 77.191,23.952 90.881,10.262 99.797,10.262 104.902,5.156 112.98,5.156 J1.8@114.369,6.546
FPGA_TMS: J1.4 MC2.7 | length 100.7
  L1-TOP w0.146: MC2.7@29.798,26.086 29.798,26.979 30.455,27.635 74.701,27.635 91.389,10.947 111.684,10.947 113.386,9.246 113.386,7.925 113.767,7.544 114.833,7.544 115.341,7.036 115.341,6.02 115.875,5.486 117.31,5.486 J1.4@118.369,6.546
MC1_1: MC1.1 MC1A.1 | length 67.3
  L1-TOP w0.146: MC1.1@62.602,70.135 v1(62.602,72.019)
  L6-BOT w0.146: v1(62.602,72.019) 63.941,72.019 71.374,79.451 92.329,79.451 98.628,85.75 109.296,85.75 114.986,91.44 114.986,94.986 MC1A.1@116,96
MC1_2: MC1.2 MC1A.2 | length 62.3
  L1-TOP w0.146: MC1.2@62.602,76.086 62.602,77.182 63.195,77.775 87.782,77.775 92.964,82.956 106.451,82.956 114.986,91.491 114.986,92.986 MC1A.2@116,94
MC1_3: MC1.3 MC1A.3 | length 66.4
  L1-TOP w0.146: v1(61.802,71.257) 61.802,70.1 MC1.3@61.849,70.053
  L6-BOT w0.146: v1(61.802,71.257) 61.802,71.853 62.419,72.47 63.301,72.47 63.576,72.746 63.576,73.127 63.856,73.406 64.262,73.406 70.841,79.985 91.846,79.985 98.501,86.639 108.306,86.639 113.03,91.364 113.03,95.03 MC1A.3@114,96
MC1_4: MC1.4 MC1A.4 | length 61.4
  L1-TOP w0.146: MC1.4@61.802,76.086 61.802,77.194 62.713,78.105 87.147,78.105 92.481,83.439 105.359,83.439 113.005,91.084 113.005,93.005 MC1A.4@114,94
MC1_5: MC1.5 MC1A.5 | length 64.9
  L1-TOP w0.146: MC1.5@61.002,70.135 v1(61.002,72.019)
  L6-BOT w0.146: v1(61.002,72.019) 61.246,72.263 61.747,72.263 63.259,73.774 64.071,73.774 70.764,80.467 91.44,80.467 98.476,87.503 107.086,87.503 110.998,91.415 110.998,94.998 MC1A.5@112,96
MC1_6: MC1.6 MC1A.6 | length 60.1
  L1-TOP w0.146: MC1.6@61.002,76.086 61.002,77.292 62.145,78.435 86.614,78.435 92.05,83.871 103.53,83.871 110.998,91.338 110.998,92.998 MC1A.6@112,94
MC1_7: MC1.7 MC1A.7 | length 63.7
  L1-TOP w0.146: v1(60.202,71.257) 60.202,70.1 MC1.7@60.249,70.053
  L6-BOT w0.146: v1(60.202,71.257) 60.202,71.813 61.083,72.695 61.773,72.695 70.155,81.077 91.135,81.077 98.298,88.24 105.893,88.24 108.991,91.338 108.991,94.991 MC1A.7@110,96
MC1_8: MC1.8 MC1A.8 | length 59
  L1-TOP w0.146: MC1.8@60.202,76.086 60.202,77.296 61.671,78.765 86.186,78.765 91.697,84.277 102.159,84.277 108.991,91.11 108.991,92.991 MC1A.8@110,94
MC1_9: MC1.9 MC1A.9 | length 62.5
  L1-TOP w0.146: MC1.9@59.402,70.135 v1(59.402,72.019)
  L6-BOT w0.146: v1(59.402,72.019) 60.009,72.019 61.194,73.203 61.671,73.203 70.079,81.61 90.83,81.61 98.019,88.798 104.419,88.798 106.959,91.338 106.959,94.959 MC1A.9@108,96
MC1_10: MC1.10 MC1A.10 | length 58
  L1-TOP w0.146: MC1.10@59.402,75.865 59.402,77.386 61.137,79.121 85.725,79.121 91.44,84.836 100.508,84.836 107,91.328 107,93 MC1A.10@108,94
MC1_11: MC1.11 MC1A.11 | length 61.7
  L1-TOP w0.146: v1(58.602,71.257) 58.602,70.1 MC1.11@58.649,70.053
  L6-BOT w0.146: v1(58.602,71.257) 58.602,71.93 59.164,72.492 59.436,72.492 59.741,72.796 59.741,73.228 60.173,73.66 61.468,73.66 69.952,82.144 90.627,82.144 97.866,89.383 103.149,89.383 105.004,91.237 105.004,95.004 MC1A.11@106,96
MC1_12: MC1.12 MC1A.12 | length 56.8
  L1-TOP w0.146: MC1.12@58.602,75.865 58.602,77.402 60.702,79.502 85.344,79.502 91.186,85.344 99.111,85.344 105.054,91.288 105.054,93.054 MC1A.12@106,94
MC1_13: MC1.13 MC1A.13 | length 60.3
  L1-TOP w0.146: MC1.13@57.802,70.135 v1(57.802,72.019)
  L6-BOT w0.146: v1(57.802,72.019) 58.674,72.891 58.674,73.13 59.585,74.041 61.087,74.041 69.698,82.652 90.373,82.652 97.561,89.84 101.422,89.84 102.997,91.415 102.997,94.997 MC1A.13@104,96
MC1_14: MC1.14 MC1A.14 | length 55.7
  L1-TOP w0.146: MC1.14@57.802,75.865 57.802,77.402 60.275,79.875 84.955,79.875 90.932,85.852 97.663,85.852 103,91.189 103,93 MC1A.14@104,94
MC1_15: MC1.15 MC1A.15 | length 59.4
  L1-TOP w0.146: v1(57.001,71.257) 57.001,70.1 MC1.15@57.048,70.053
  L6-BOT w0.146: v1(57.001,71.257) 57.001,72.114 57.531,72.644 57.531,73.025 58.903,74.397 60.681,74.397 69.469,83.185 90.297,83.185 97.46,90.348 100.072,90.348 101.016,91.291 101.016,95.016 MC1A.15@102,96
MC1_16: MC1.16 MC1A.16 | length 54.5
  L1-TOP w0.146: MC1.16@57.001,75.865 57.001,77.401 59.864,80.264 84.582,80.264 90.678,86.36 96.164,86.36 100.99,91.186 100.99,92.99 MC1A.16@102,94
MC1_17: MC1.17 MC1A.17 | length 58.2
  L1-TOP w0.146: MC1.17@56.201,70.135 v1(56.201,72.019)
  L6-BOT w0.146: v1(56.201,72.019) 56.591,72.408 56.591,73.254 58.141,74.803 60.325,74.803 69.215,83.693 90.145,83.693 97.271,90.82 98.334,90.82 98.984,91.469 98.984,94.984 MC1A.17@100,96
MC1_18: MC1.18 MC1A.18 | length 53.3
  L1-TOP w0.146: MC1.18@56.201,75.865 56.201,77.401 59.445,80.645 84.201,80.645 90.424,86.868 94.687,86.868 98.984,91.164 98.984,92.984 MC1A.18@100,94
MC1_19: MC1.19 MC1A.19 | length 57.5
  L1-TOP w0.146: v1(55.401,71.257) 55.401,70.024 MC1.19@55.474,69.952
  L6-BOT w0.146: v1(55.401,71.257) 55.401,73.029 57.607,75.235 59.995,75.235 68.961,84.201 90.014,84.201 96.952,91.139 96.952,94.952 MC1A.19@98,96
MC1_20: MC1.20 MC1A.20 | length 52.1
  L1-TOP w0.146: MC1.20@55.401,75.865 55.401,77.401 59.026,81.026 83.82,81.026 90.209,87.415 93.232,87.415 96.977,91.161 96.977,92.977 MC1A.20@98,94
MC1_21: MC1.21 MC1A.21 | length 55.7
  L1-TOP w0.146: MC1.21@54.601,70.135 v1(54.601,72.019)
  L6-BOT w0.146: v1(54.601,72.019) 54.966,72.383 54.966,73.148 57.56,75.743 59.741,75.743 68.707,84.709 88.236,84.709 95.021,91.495 95.021,95.021 MC1A.21@96,96
MC1_22: MC1.22 MC1A.22 | length 50.8
  L1-TOP w0.146: MC1.22@54.601,75.865 54.601,77.401 58.607,81.407 83.439,81.407 89.916,87.884 91.589,87.884 94.996,91.291 94.996,92.996 MC1A.22@96,94
MC1_23: MC1.23 MC1A.23 | length 54.7
  L1-TOP w0.146: v1(53.801,71.257) 53.801,70.011 MC1.23@53.848,69.964
  L6-BOT w0.146: v1(53.801,71.257) 53.801,71.864 54.356,72.419 54.356,73.127 57.429,76.2 59.436,76.2 68.453,85.217 86.915,85.217 92.989,91.291 92.989,94.989 MC1A.23@94,96
MC1_24: MC1.24 MC1A.24 | length 49.7
  L1-TOP w0.146: MC1.24@53.801,75.865 53.801,77.401 58.188,81.788 83.058,81.788 89.662,88.392 90.192,88.392 92.989,91.19 92.989,92.989 MC1A.24@94,94
MC1_25: MC1.25 MC1A.25 | length 53.3
  L1-TOP w0.146: MC1.25@53.001,70.135 v1(53.001,72.019)
  L6-BOT w0.146: v1(53.001,72.019) 53.4,72.019 53.873,72.492 53.873,73.254 57.226,76.606 59.08,76.606 68.199,85.725 85.264,85.725 91.008,91.469 91.008,95.008 MC1A.25@92,96
MC1_26: MC1.26 MC1A.26 | length 48.4
  L1-TOP w0.146: MC1.26@53.001,75.865 53.001,77.401 57.769,82.169 81.911,82.169 91.008,91.266 91.008,93.008 MC1A.26@92,94
MC1_27: MC1.27 MC1A.27 | length 52.3
  L1-TOP w0.146: MC1.27@52.172,69.935 52.201,69.964 v1(52.201,71.257)
  L6-BOT w0.146: v1(52.201,71.257) 52.201,71.94 52.807,72.546 53.178,72.546 53.416,72.784 53.416,73.508 57.017,77.108 58.82,77.108 67.945,86.233 83.791,86.233 89.027,91.469 89.027,95.027 MC1A.27@90,96
MC1_28: MC1.28 MC1A.28 | length 47.2
  L1-TOP w0.146: MC1.28@52.201,75.865 52.201,77.401 57.35,82.55 80.209,82.55 88.976,91.317 88.976,92.976 MC1A.28@90,94
MC1_29: MC1.29 MC1A.29 | length 50.9
  L1-TOP w0.146: MC1.29@51.401,70.135 v1(51.401,72.019)
  L6-BOT w0.146: v1(51.401,72.019) 51.771,72.019 52.299,72.546 52.299,73.283 56.616,77.6 58.55,77.6 67.691,86.741 82.318,86.741 87.046,91.469 87.046,95.046 MC1A.29@88,96
MC1_30: MC1.30 MC1A.30 | length 46.1
  L1-TOP w0.146: MC1.30@51.401,75.865 51.401,77.401 56.931,82.931 78.791,82.931 86.995,91.135 86.995,92.995 MC1A.30@88,94
MC1_31: MC1.31 MC1A.31 | length 50
  L1-TOP w0.146: MC1.31@50.597,69.91 MC1.31@50.601,69.914 v1(50.601,71.257)
  L6-BOT w0.146: v1(50.601,71.257) 50.601,71.94 51.283,72.622 51.283,73.092 56.375,78.185 58.373,78.185 67.437,87.249 81.2,87.249 85.014,91.063 85.014,95.014 MC1A.31@86,96
MC1_32: MC1.32 MC1A.32 | length 44.9
  L1-TOP w0.146: MC1.32@50.601,75.865 50.601,77.401 56.512,83.312 77.161,83.312 84.988,91.139 84.988,92.988 MC1A.32@86,94
MC1_33: MC1.33 MC1A.33 | length 48.6
  L1-TOP w0.146: MC1.33@49.801,70.135 v1(49.801,72.019)
  L6-BOT w0.146: v1(49.801,72.019) 50.216,72.434 50.216,73.13 55.855,78.769 58.195,78.769 67.183,87.757 79.473,87.757 83.033,91.317 83.033,95.033 MC1A.33@84,96
MC1_34: MC1.34 MC1A.34 | length 43.7
  L1-TOP w0.146: MC1.34@49.801,75.865 49.801,77.401 56.093,83.693 75.54,83.693 83.007,91.161 83.007,93.007 MC1A.34@84,94
MC1_35: MC1.35 MC1A.35 | length 47.9
  L1-TOP w0.146: v1(49,71.257) 49,69.986 49.022,69.964 49.022,70.028 MC1.35@49.073,70.079
  L6-BOT w0.146: v1(49,71.257) 49,72.982 55.619,79.6 58.264,79.6 66.929,88.265 78.076,88.265 81.001,91.19 81.001,95.001 MC1A.35@82,96
MC1_36: MC1.36 MC1A.36 | length 42.4
  L1-TOP w0.146: MC1.36@49,75.865 49,77.4 55.674,84.074 73.812,84.074 80.975,91.237 80.975,92.975 MC1A.36@82,94
MC1_37: MC1.37 MC1A.37 | length 46.3
  L1-TOP w0.146: MC1.37@48.2,70.135 v1(48.2,72.019)
  L6-BOT w0.146: v1(48.2,72.019) 48.641,72.459 48.641,73.273 55.768,80.4 58.302,80.4 66.675,88.773 76.603,88.773 79.019,91.19 79.019,95.019 MC1A.37@80,96
MC1_38: MC1.38 MC1A.38 | length 41.2
  L1-TOP w0.146: MC1.38@48.2,75.865 48.2,77.402 55.253,84.455 72.208,84.455 79.019,91.266 79.019,93.019 MC1A.38@80,94
MC1_39: MC1.39 MC1A.39 | length 43.3
  L1-TOP w0.146: MC1.39@47.371,69.935 47.4,69.964 v1(47.4,71.257)
  L6-BOT w0.146: v1(47.4,71.257) 47.4,73.092 55.508,81.2 58.34,81.2 66.421,89.281 71.281,89.281 MC1A.39@78,96
MC1_40: MC1.40 MC1A.40 | length 39
  L1-TOP w0.146: MC1.40@47.4,75.865 47.4,77.4 54.836,84.836 67.488,84.836 76.652,94 MC1A.40@78,94
MC1_41: MC1.41 MC1B.1 | length 43
  L1-TOP w0.146: MC1.41@42.6,70.135 v1(42.6,72.019)
  L6-BOT w0.146: v1(42.6,72.019) 42.6,73.334 51.266,82 58.378,82 66.167,89.789 68.189,89.789 70,91.6 70,95 MC1B.1@71,96
MC1_42: MC1.42 MC1B.2 | length 37.9
  L1-TOP w0.146: MC1.42@42.6,75.865 42.6,77.4 50.417,85.217 64.055,85.217 70,91.162 70,93 MC1B.2@71,94
MC1_43: MC1.43 MC1B.3 | length 42.4
  L1-TOP w0.146: v1(41.8,71.257) 41.8,70.011 MC1.43@41.834,69.977
  L6-BOT w0.146: v1(41.8,71.257) 41.8,72.149 41.478,72.47 41.478,73.292 50.987,82.8 58.416,82.8 65.913,90.297 66.697,90.297 67.996,91.596 67.996,94.996 MC1B.3@69,96
MC1_44: MC1.44 MC1B.4 | length 36.6
  L1-TOP w0.146: MC1.44@41.8,75.865 41.8,77.4 49.998,85.598 62.302,85.598 68,91.296 68,93 MC1B.4@69,94
MC1_45: MC1.45 MC1B.5 | length 40.6
  L1-TOP w0.146: MC1.45@40.999,70.135 v1(40.999,72.019)
  L6-BOT w0.146: v1(40.999,72.019) 40.999,72.398 41.123,72.521 41.123,73.523 51.2,83.6 58,83.6 65.989,91.589 65.989,94.989 MC1B.5@67,96
MC1_46: MC1.46 MC1B.6 | length 35.4
  L1-TOP w0.146: MC1.46@40.999,75.865 40.999,77.399 49.579,85.979 60.702,85.979 66.015,91.291 66.015,93.015 MC1B.6@67,94
MC1_47: MC1.47 MC1B.7 | length 39.5
  L1-TOP w0.146: v1(40.199,71.257) 40.199,69.995 MC1.47@40.208,69.986
  L6-BOT w0.146: v1(40.199,71.257) 40.199,72.08 40.742,72.622 40.742,73.762 51.38,84.4 56.8,84.4 63.983,91.583 63.983,94.983 MC1B.7@65,96
MC1_48: MC1.48 MC1B.8 | length 34.2
  L1-TOP w0.146: MC1.48@40.199,75.865 40.199,77.399 49.16,86.36 59.051,86.36 64,91.309 64,93 MC1B.8@65,94
MC1_49: MC1.49 MC1B.9 | length 38.1
  L1-TOP w0.146: MC1.49@39.399,70.135 v1(39.399,72.019)
  L6-BOT w0.146: v1(39.399,72.019) 39.7,72.32 39.7,73.482 51.418,85.2 55.6,85.2 62.027,91.627 62.027,95.027 MC1B.9@63,96
MC1_50: MC1.50 MC1B.10 | length 33.1
  L1-TOP w0.146: MC1.50@39.399,75.865 39.399,77.399 48.741,86.741 57.629,86.741 62.01,91.123 62.01,93.01 MC1B.10@63,94
MC1_51: MC1.51 MC1B.11 | length 37.3
  L1-TOP w0.146: MC1.51@38.599,69.986 v1(38.599,71.257)
  L6-BOT w0.146: v1(38.599,71.257) 38.599,72.512 38.71,72.622 38.71,73.505 51.205,86 54.551,86 60.02,91.469 60.02,95.02 MC1B.11@61,96
MC1_52: MC1.52 MC1B.12 | length 31.8
  L1-TOP w0.146: MC1.52@38.599,75.865 38.599,77.399 48.322,87.122 55.775,87.122 60.02,91.368 60.02,93.02 MC1B.12@61,94
MC1_53: MC1.53 MC1B.13 | length 36.1
  L1-TOP w0.146: MC1.53@37.799,70.135 v1(37.799,72.019)
  L6-BOT w0.146: v1(37.799,72.019) 37.799,72.339 37.668,72.47 37.668,73.268 51.2,86.8 53.548,86.8 58.014,91.266 58.014,95.014 MC1B.13@59,96
MC1_54: MC1.54 MC1B.14 | length 30.7
  L1-TOP w0.146: MC1.54@37.799,75.865 37.799,77.399 47.903,87.503 54.378,87.503 58,91.125 58,93 MC1B.14@59,94
MC1_55: MC1.55 MC1B.15 | length 35.6
  L1-TOP w0.146: v1(36.999,71.257) 36.999,69.935 MC1.55@37.059,69.875
  L6-BOT w0.146: v1(36.999,71.257) 36.999,72.241 36.601,72.639 36.601,73.444 50.757,87.6 52.112,87.6 56.058,91.545 56.058,95.058 MC1B.15@57,96
MC1_56: MC1.56 MC1B.16 | length 29.4
  L1-TOP w0.146: MC1.56@36.999,75.865 36.999,77.399 47.484,87.884 52.498,87.884 56.007,91.393 56.007,93.007 MC1B.16@57,94
MC1_57: MC1.57 MC1B.17 | length 34.2
  L1-TOP w0.146: MC1.57@36.199,70.135 v1(36.199,72.019)
  L6-BOT w0.146: v1(36.199,72.019) 35.56,72.657 35.56,73.228 54.026,91.694 54.026,95.026 MC1B.17@55,96
MC1_58: MC1.58 MC1B.18 | length 28.2
  L1-TOP w0.146: MC1.58@36.199,75.865 36.199,77.399 47.065,88.265 50.923,88.265 54,91.342 54,93 MC1B.18@55,94
MC1_59: MC1.59 MC1B.19 | length 33.7
  L1-TOP w0.146: v1(35.399,71.257) 35.399,69.935 MC1.59@35.509,69.825
  L6-BOT w0.146: v1(35.399,71.257) 35.399,71.615 35.23,71.784 35.23,74.654 52.045,91.469 52.045,95.045 MC1B.19@53,96
MC1_60: MC1.60 MC1B.20 | length 26.9
  L1-TOP w0.146: MC1.60@35.399,75.865 35.399,77.399 46.646,88.646 49.145,88.646 52.019,91.52 52.019,93.019 MC1B.20@53,94
MC1_61: MC1.61 MC1B.21 | length 32.7
  L1-TOP w0.146: MC1.61@34.599,70.135 v1(34.599,72.019)
  L6-BOT w0.146: v1(34.599,72.019) 34.823,72.243 34.823,75.924 49.962,91.063 49.962,94.962 MC1B.21@51,96
MC1_62: MC1.62 MC1B.22 | length 25.8
  L1-TOP w0.146: MC1.62@34.599,75.865 34.599,77.399 46.227,89.027 47.647,89.027 50.013,91.393 50.013,93.013 MC1B.22@51,94
MC1_63: MC1.63 MC1B.23 | length 32.4
  L1-TOP w0.146: v1(33.799,71.257) 33.799,69.986 MC1.63@33.833,69.952
  L6-BOT w0.146: v1(33.799,71.257) 33.799,71.902 34.417,72.521 34.417,78.017 47.99,91.59 47.99,94.99 MC1B.23@49,96
MC1_64: MC1.64 MC1B.24 | length 24.6
  L1-TOP w0.146: MC1.64@33.799,75.865 33.799,77.399 45.808,89.408 46.021,89.408 48.006,91.393 48.006,93.006 MC1B.24@49,94
MC1_65: MC1.65 MC1B.25 | length 32
  L1-TOP w0.146: MC1.65@32.998,70.135 v1(32.998,72.019)
  L6-BOT w0.146: v1(32.998,72.019) 33.376,72.396 33.376,73.261 32.998,73.638 32.998,78.598 46.05,91.65 46.05,95.05 MC1B.25@47,96
MC1_66: MC1.66 MC1B.26 | length 23.9
  L1-TOP w0.146: MC1.66@32.998,75.865 32.998,78.596 46.025,91.623 46.025,93.025 MC1B.26@47,94
MC1_68: MC1.68 MC1B.28 | length 23.4
  L1-TOP w0.146: MC1.68@32.198,75.865 32.198,79.798 44.018,91.618 44.018,93.018 MC1B.28@45,94
MC1_70: MC1.70 MC1B.30 | length 22.9
  L1-TOP w0.146: MC1.70@31.398,75.865 31.398,80.998 41.961,91.561 41.961,92.961 MC1B.30@43,94
MC1_72: MC1.72 MC1B.32 | length 22.4
  L1-TOP w0.146: MC1.72@30.598,75.865 30.598,82.198 40.005,91.605 40.005,93.005 MC1B.32@41,94
MC2_10: MC2.10 MC2A.10 | length 18.1
  L1-TOP w0.146: MC2A.10@21,6 21.996,6.996 21.996,9.656 30.598,18.258 MC2.10@30.598,20.135
MC2_11: MC2.11 MC2A.11 | length 25.6
  L1-TOP w0.146: v1(31.398,23.981) MC2.11@31.398,25.865
  L6-BOT w0.146: MC2A.11@23,4 24.028,5.028 24.028,13.106 30.277,19.355 30.277,23.249 31.01,23.981 v1(31.398,23.981)
MC2_12: MC2.12 MC2A.12 | length 17.6
  L1-TOP w0.146: MC2A.12@23,6 24.028,7.028 24.028,10.85 31.398,18.219 MC2.12@31.398,20.135
MC2_13: MC2.13 MC2A.13 | length 25
  L1-TOP w0.146: v1(32.198,24.743) 32.198,25.975 MC2.13@32.258,26.035
  L6-BOT w0.146: MC2A.13@25,4 25.984,4.984 25.984,14.275 31.293,19.583 31.293,23.165 32.198,24.07 v1(32.198,24.743)
MC2_14: MC2.14 MC2A.14 | length 17.1
  L1-TOP w0.146: MC2A.14@25,6 26.01,7.01 26.01,11.739 32.198,17.927 MC2.14@32.198,20.135
MC2_15: MC2.15 MC2A.15 | length 24.3
  L1-TOP w0.146: v1(32.998,23.981) MC2.15@32.998,25.865
  L6-BOT w0.146: MC2A.15@27,4 28.016,5.016 28.016,15.367 32.36,19.71 32.36,23.343 v1(32.998,23.981)
MC2_16: MC2.16 MC2A.16 | length 16.6
  L1-TOP w0.146: MC2A.16@27,6 28.016,7.016 28.016,12.628 32.998,17.61 MC2.16@32.998,20.135
MC2_17: MC2.17 MC2A.17 | length 24
  L1-TOP w0.146: v1(33.799,24.743) MC2.17@33.799,26.052
  L6-BOT w0.146: MC2A.17@29,4 29.997,4.997 29.997,16.408 33.401,19.812 33.401,23.727 33.799,24.125 v1(33.799,24.743)
MC2_18: MC2.18 MC2A.18 | length 16.1
  L1-TOP w0.146: MC2A.18@29,6 29.997,6.997 29.997,13.466 33.799,17.267 MC2.18@33.799,20.135
MC2_19: MC2.19 MC2A.19 | length 23.4
  L1-TOP w0.146: v1(34.599,23.981) MC2.19@34.599,25.865
  L6-BOT w0.146: MC2A.19@31,4 32.055,5.055 32.055,17.196 34.599,19.74 v1(34.599,23.981)
MC2_20: MC2.20 MC2A.20 | length 15.6
  L1-TOP w0.146: MC2A.20@31,6 32.004,7.004 32.004,14.355 34.599,16.949 MC2.20@34.599,20.135
MC2_21: MC2.21 MC2A.21 | length 23
  L1-TOP w0.146: MC2.21@35.357,25.975 35.399,25.933 v1(35.399,24.743)
  L6-BOT w0.146: MC2A.21@33,4 33.985,4.985 33.985,17.971 35.179,19.165 35.179,24.138 35.399,24.357 v1(35.399,24.743)
MC2_22: MC2.22 MC2A.22 | length 15.1
  L1-TOP w0.146: MC2A.22@33,6 33.985,6.985 33.985,15.117 35.399,16.53 MC2.22@35.399,20.135
MC2_23: MC2.23 MC2A.23 | length 22.7
  L1-TOP w0.146: v1(36.199,23.981) MC2.23@36.199,25.865
  L6-BOT w0.146: MC2A.23@35,4 36.043,5.043 36.043,21.619 35.611,22.051 35.611,23.393 v1(36.199,23.981)
MC2_24: MC2.24 MC2A.24 | length 14.6
  L1-TOP w0.146: MC2A.24@35,6 36.043,7.043 36.043,16.184 36.199,16.34 MC2.24@36.199,20.135
MC2_25: MC2.25 MC2A.25 | length 23.3
  L1-TOP w0.146: v1(36.999,24.743) 36.999,26.052 MC2.25@37.033,26.086
  L6-BOT w0.146: v1(36.999,24.743) 36.999,24.261 36.601,23.863 36.601,21.819 38.024,20.396 38.024,5.024 MC2A.25@37,4
MC2_26: MC2.26 MC2A.26 | length 15
  L1-TOP w0.146: MC2.26@36.999,20.135 36.999,9.969 38.024,8.945 38.024,7.024 MC2A.26@37,6
MC2_27: MC2.27 MC2A.27 | length 23.4
  L1-TOP w0.146: v1(37.799,23.981) MC2.27@37.799,25.865
  L6-BOT w0.146: v1(37.799,23.981) 37.643,23.825 37.643,22.047 40.056,19.634 40.056,5.056 MC2A.27@39,4
MC2_28: MC2.28 MC2A.28 | length 15.5
  L1-TOP w0.146: MC2.28@37.799,20.135 37.799,10.846 40.005,8.64 40.005,7.005 MC2A.28@39,6
MC2_29: MC2.29 MC2A.29 | length 23.8
  L1-TOP w0.146: MC2.29@38.583,26.01 38.599,25.993 v1(38.599,24.743)
  L6-BOT w0.146: v1(38.599,24.743) 38.599,24.143 38.71,24.032 38.71,22.25 41.961,18.999 41.961,4.961 MC2A.29@41,4
MC2_30: MC2.30 MC2A.30 | length 16
  L1-TOP w0.146: MC2.30@38.599,20.135 38.599,12.103 42.012,8.691 42.012,7.012 MC2A.30@41,6
MC2_31: MC2.31 MC2A.31 | length 24.2
  L1-TOP w0.146: v1(39.399,23.981) MC2.31@39.399,25.865
  L6-BOT w0.146: v1(39.399,23.981) 39.751,23.63 39.751,22.225 44.018,17.958 44.018,5.018 MC2A.31@43,4
MC2_32: MC2.32 MC2A.32 | length 16.5
  L1-TOP w0.146: MC2.32@39.399,20.135 39.399,13.233 44.018,8.614 44.018,7.018 MC2A.32@43,6
MC2_33: MC2.33 MC2A.33 | length 24.9
  L1-TOP w0.146: v1(40.199,24.743) 40.199,26.026 MC2.33@40.234,26.06
  L6-BOT w0.146: v1(40.199,24.743) 40.199,23.965 40.945,23.219 40.945,22.047 46.025,16.967 46.025,5.025 MC2A.33@45,4
MC2_34: MC2.34 MC2A.34 | length 16.9
  L1-TOP w0.146: MC2.34@40.199,20.135 40.199,14.491 45.974,8.716 45.974,6.974 MC2A.34@45,6
MC2_35: MC2.35 MC2A.35 | length 25.2
  L1-TOP w0.146: v1(40.999,23.981) MC2.35@40.999,25.865
  L6-BOT w0.146: v1(40.999,23.981) 41.453,23.528 41.453,22.555 47.99,16.018 47.99,4.99 MC2A.35@47,4
MC2_36: MC2.36 MC2A.36 | length 17.5
  L1-TOP w0.146: MC2.36@40.999,20.135 40.999,15.672 48.006,8.665 48.006,7.006 MC2A.36@47,6
MC2_37: MC2.37 MC2A.37 | length 25.8
  L1-TOP w0.146: MC2.37@41.758,26.035 41.8,25.993 v1(41.8,24.743)
  L6-BOT w0.146: v1(41.8,24.743) 41.8,24.092 42.52,23.372 42.52,22.504 49.962,15.062 49.962,4.962 MC2A.37@49,4
MC2_38: MC2.38 MC2A.38 | length 18
  L1-TOP w0.146: MC2.38@41.8,20.135 41.8,16.98 50.013,8.767 50.013,7.013 MC2A.38@49,6
MC2_39: MC2.39 MC2A.39 | length 26.5
  L1-TOP w0.146: v1(42.6,23.981) MC2.39@42.6,25.865
  L6-BOT w0.146: v1(42.6,23.981) 42.925,23.981 43.586,23.32 43.586,22.454 52.197,13.843 52.197,5.197 MC2A.39@51,4
MC2_40: MC2.40 MC2A.40 | length 18.6
  L1-TOP w0.146: MC2.40@42.6,20.135 42.6,18.288 52.146,8.741 52.146,7.146 MC2A.40@51,6
MC2_41: MC2.41 MC2B.1 | length 26.5
  L1-TOP w0.146: v1(47.4,24.743) 47.4,26.039 MC2.41@47.422,26.06
  L6-BOT w0.146: v1(47.4,24.743) 47.4,24.286 47.473,24.214 47.473,19.583 56.667,10.389 56.667,5.333 MC2B.1@58,4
